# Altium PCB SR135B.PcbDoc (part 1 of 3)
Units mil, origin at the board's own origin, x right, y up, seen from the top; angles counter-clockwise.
Board outline 4100 x 3600 mil, 4 copper layers (Top Layer, Signal Layer 1, Signal Layer 2, Bottom Layer), stack 73.068 mil thick; 169 components, 61 nets, 392 pads, 261 vias.
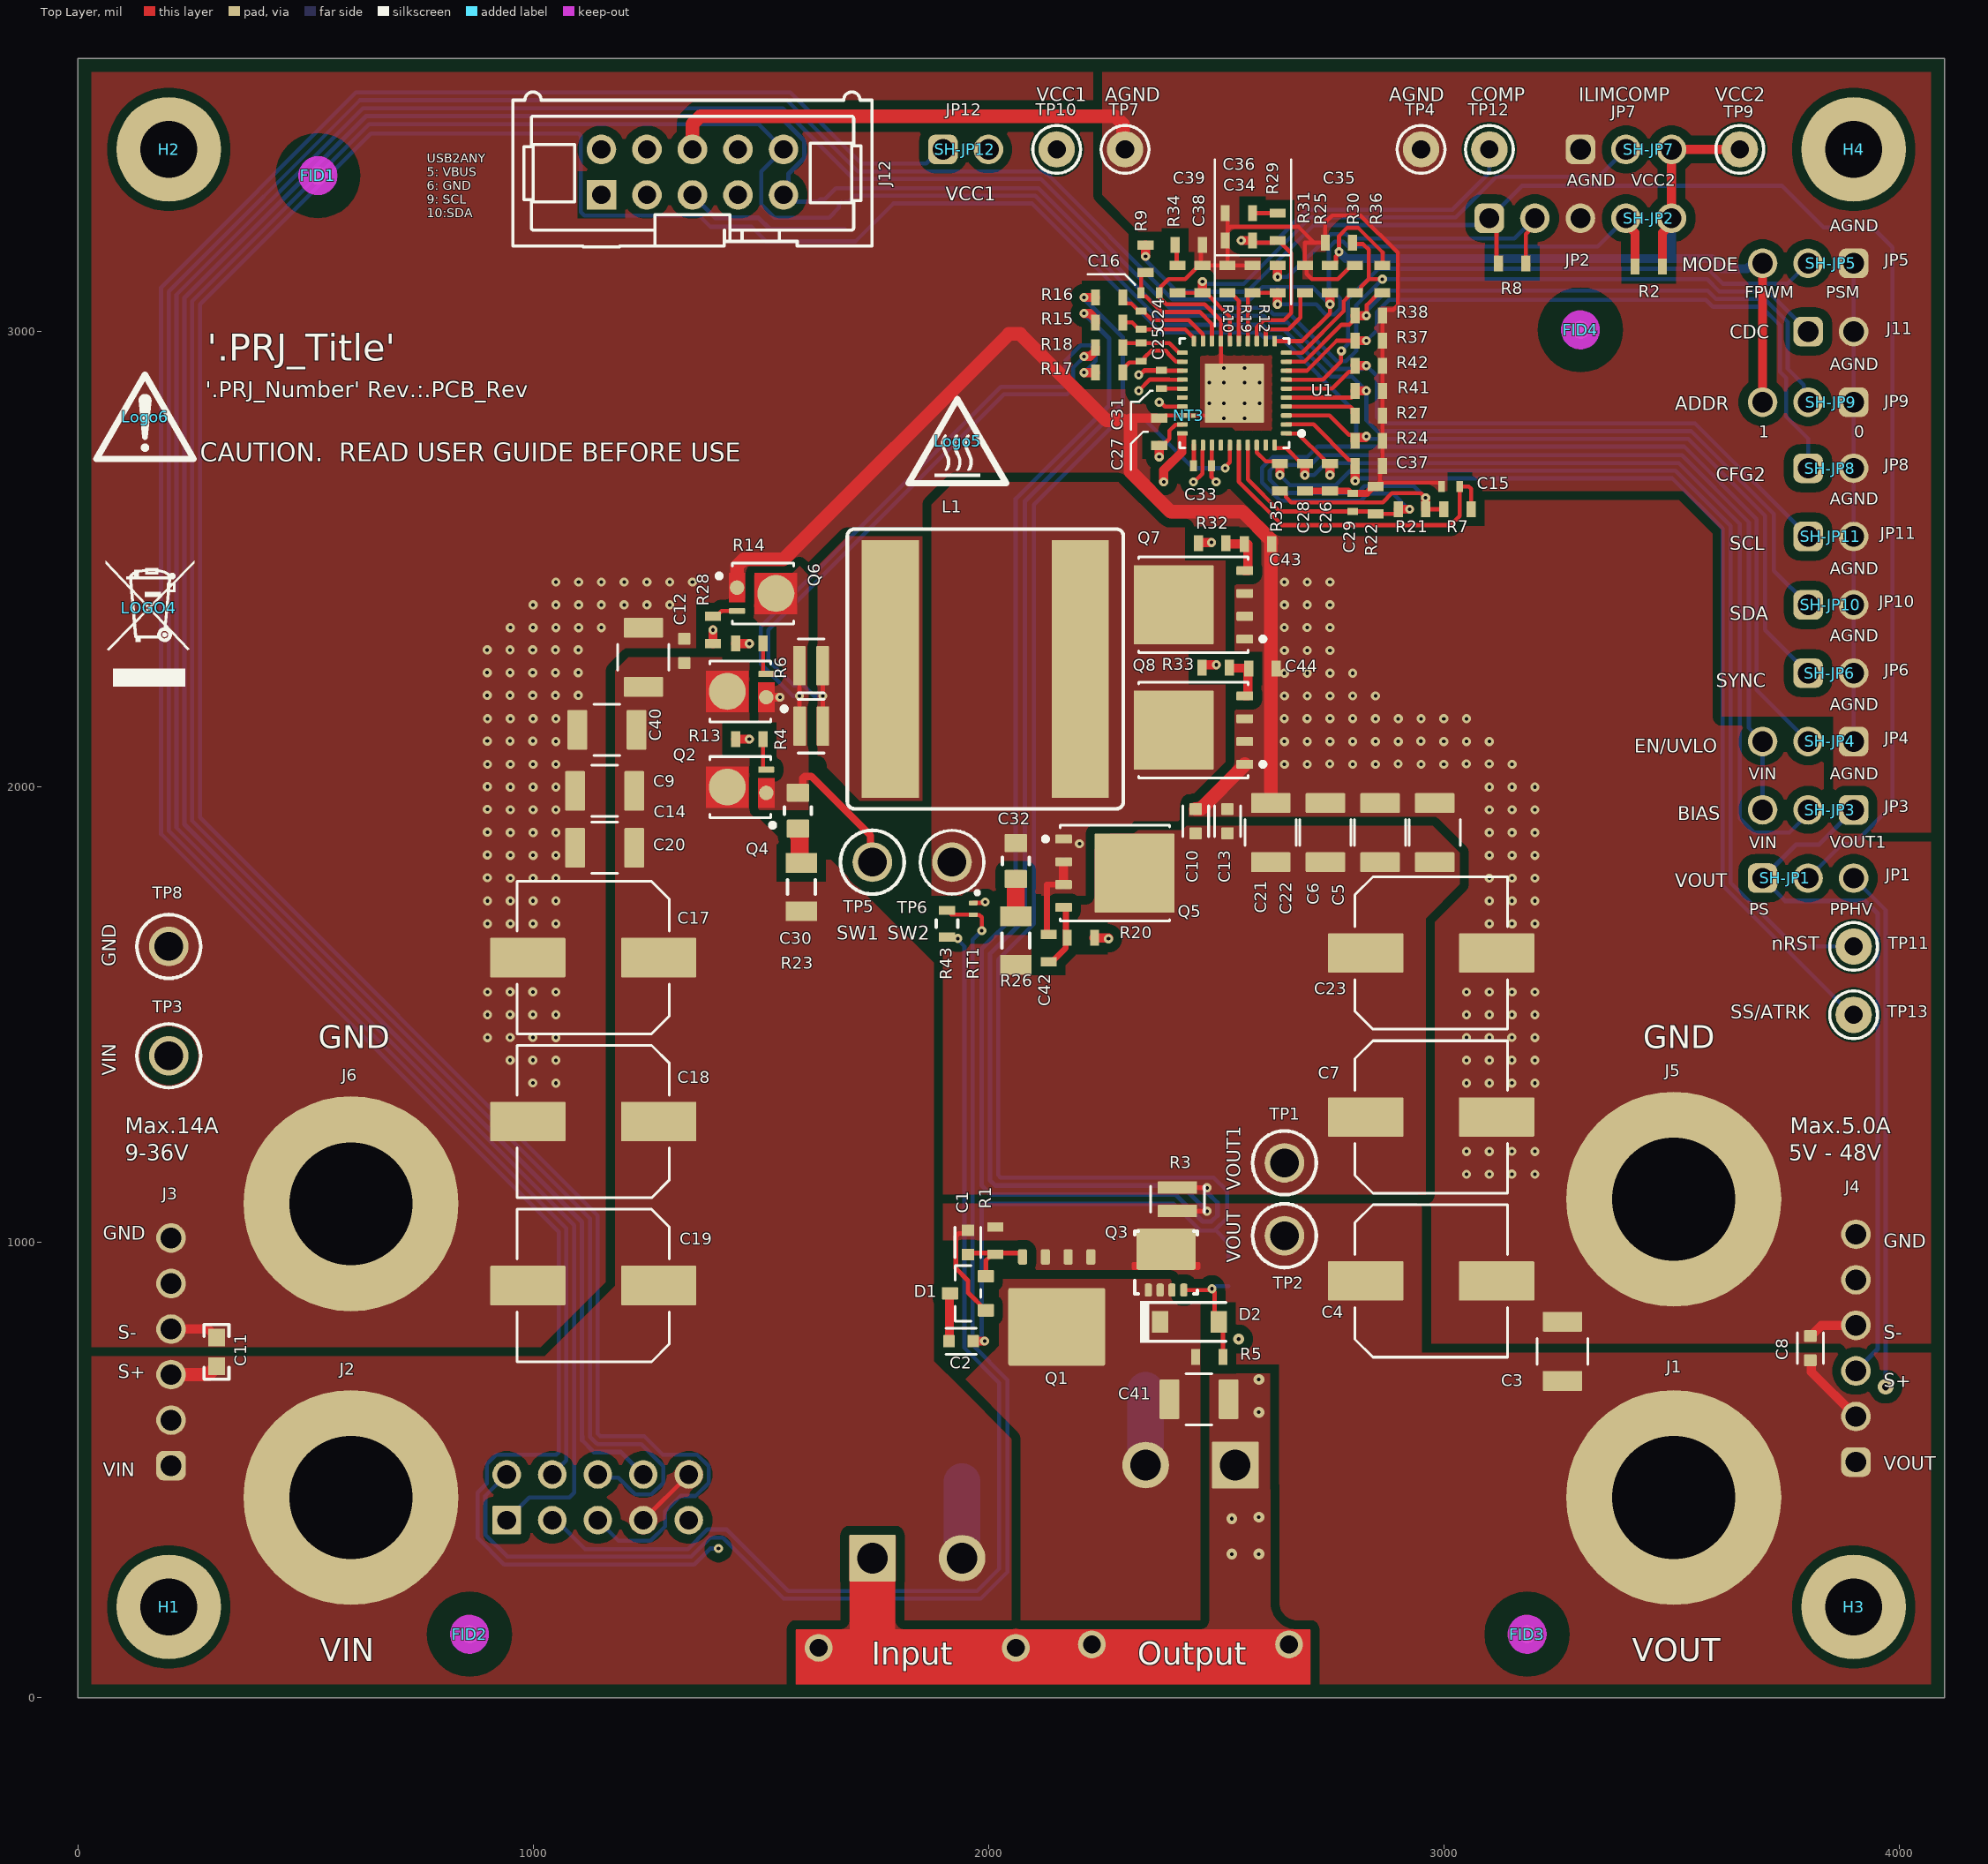
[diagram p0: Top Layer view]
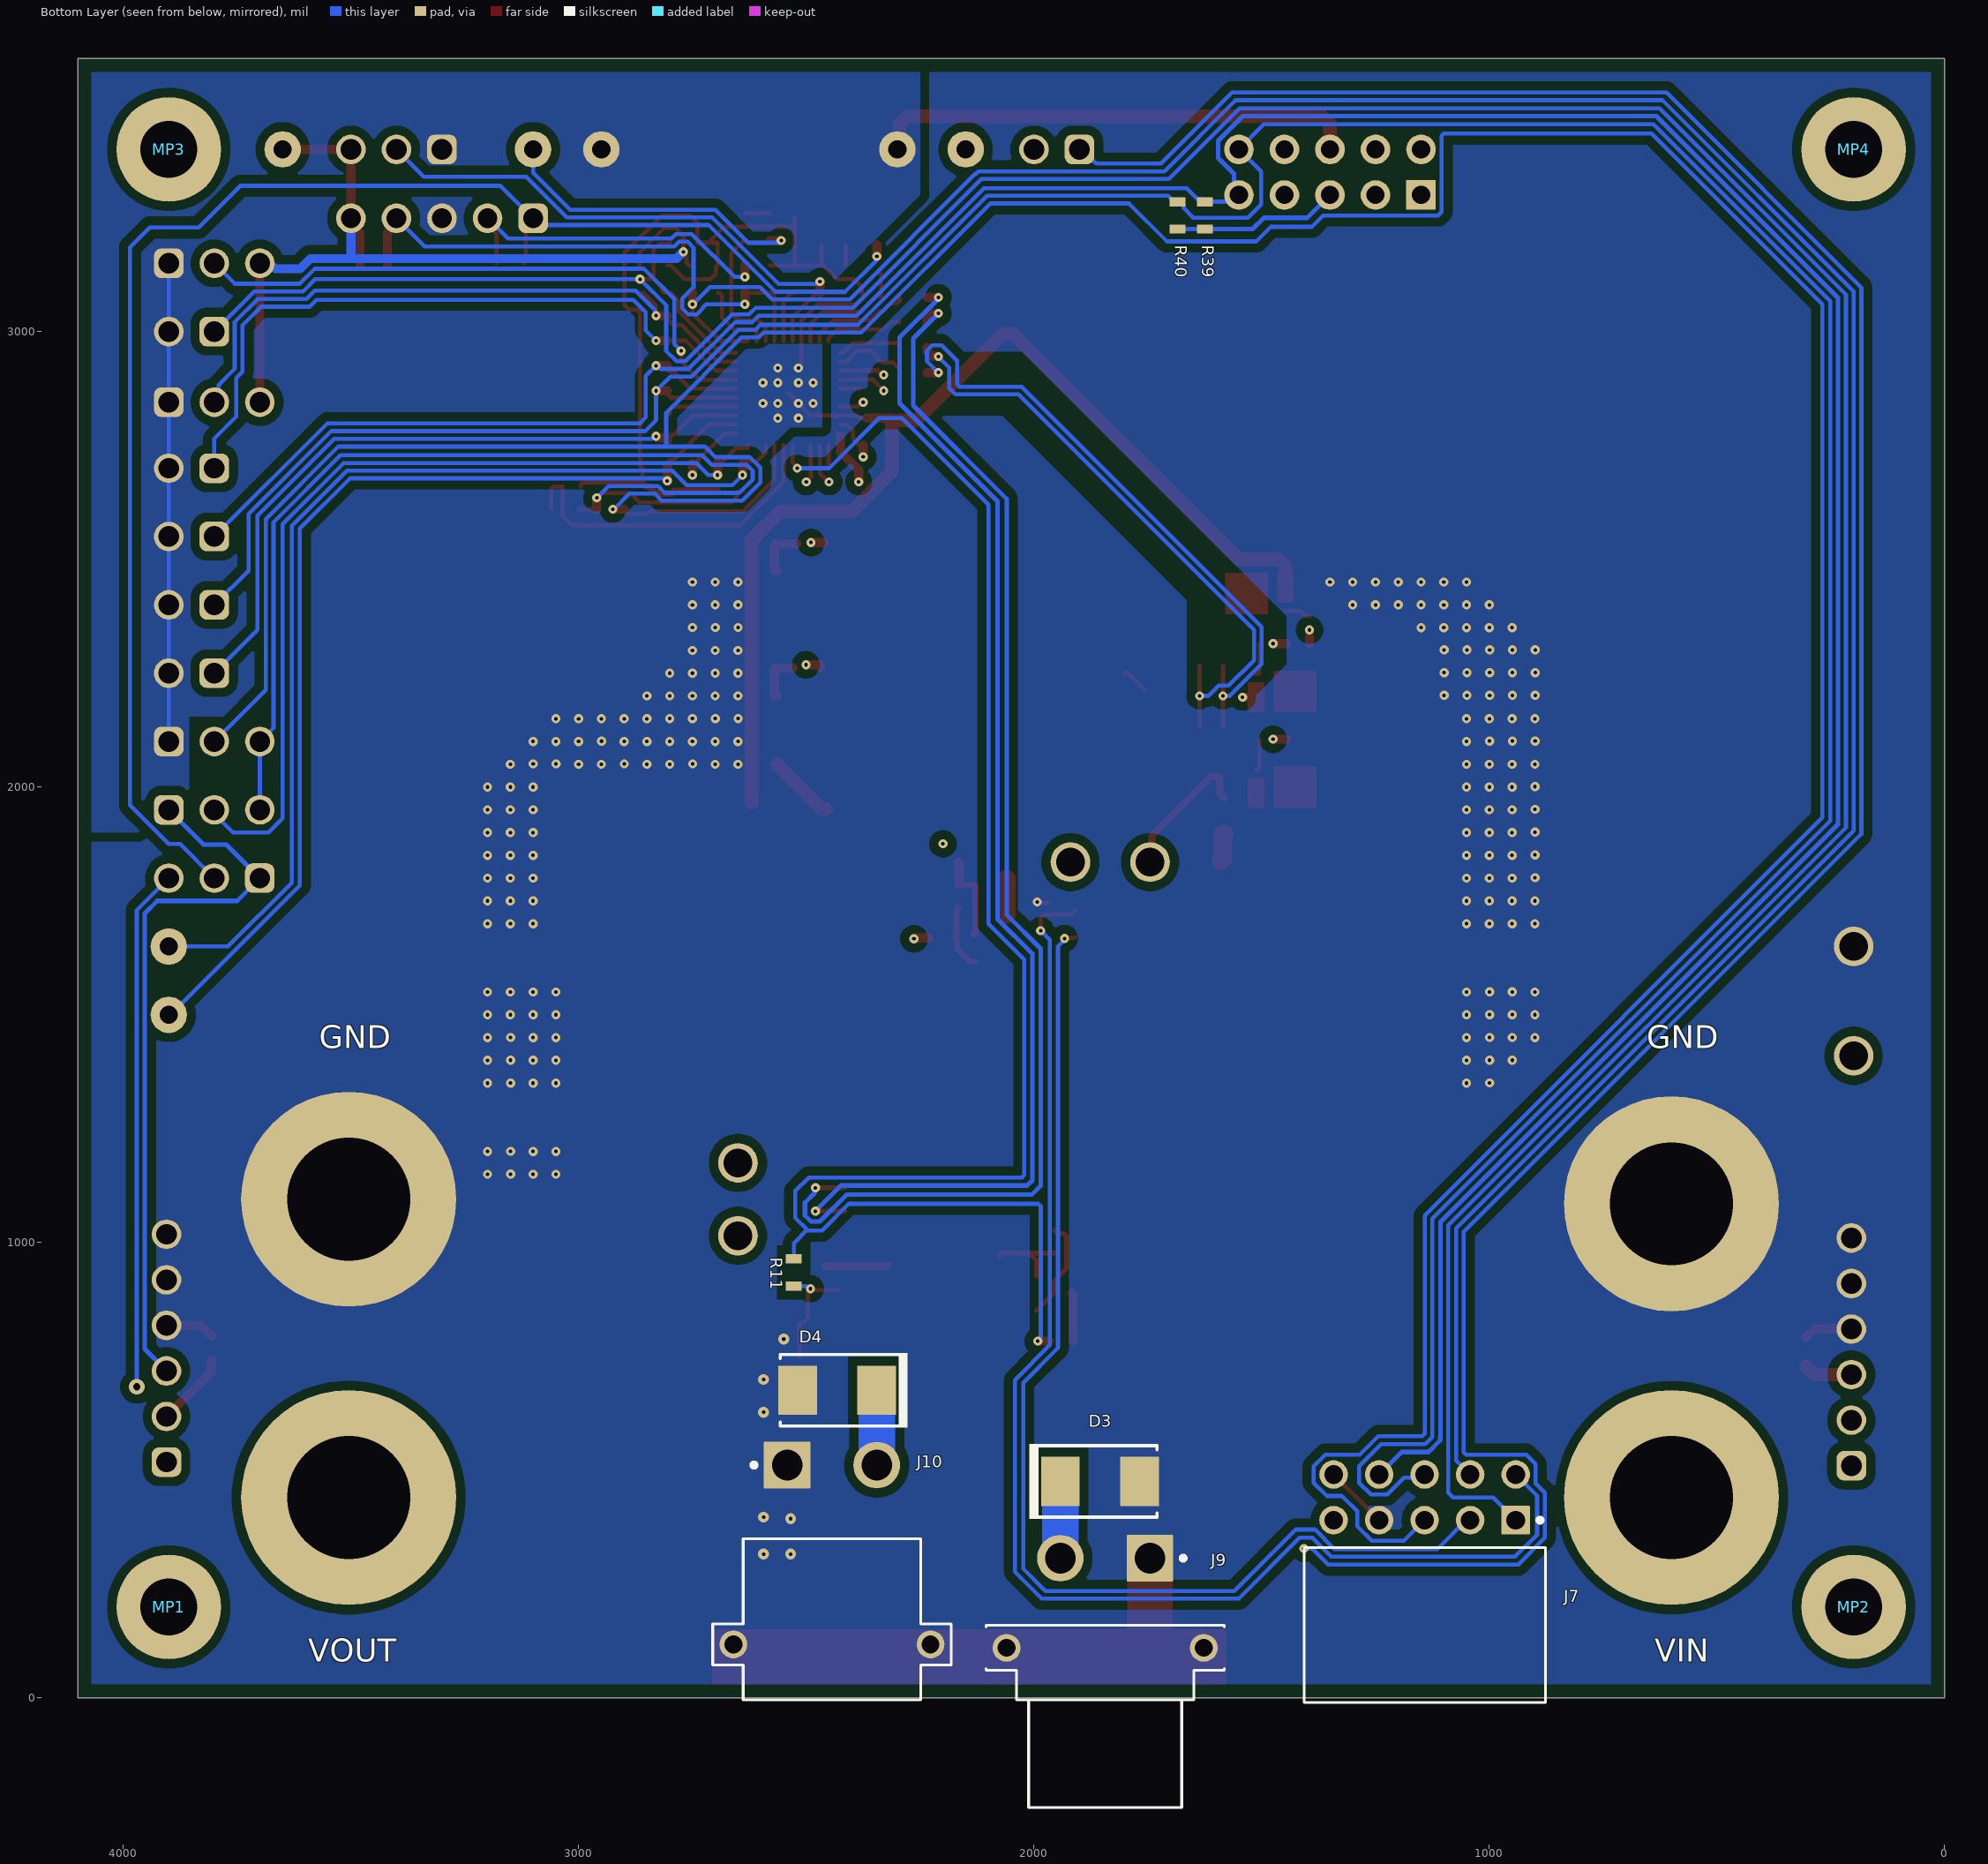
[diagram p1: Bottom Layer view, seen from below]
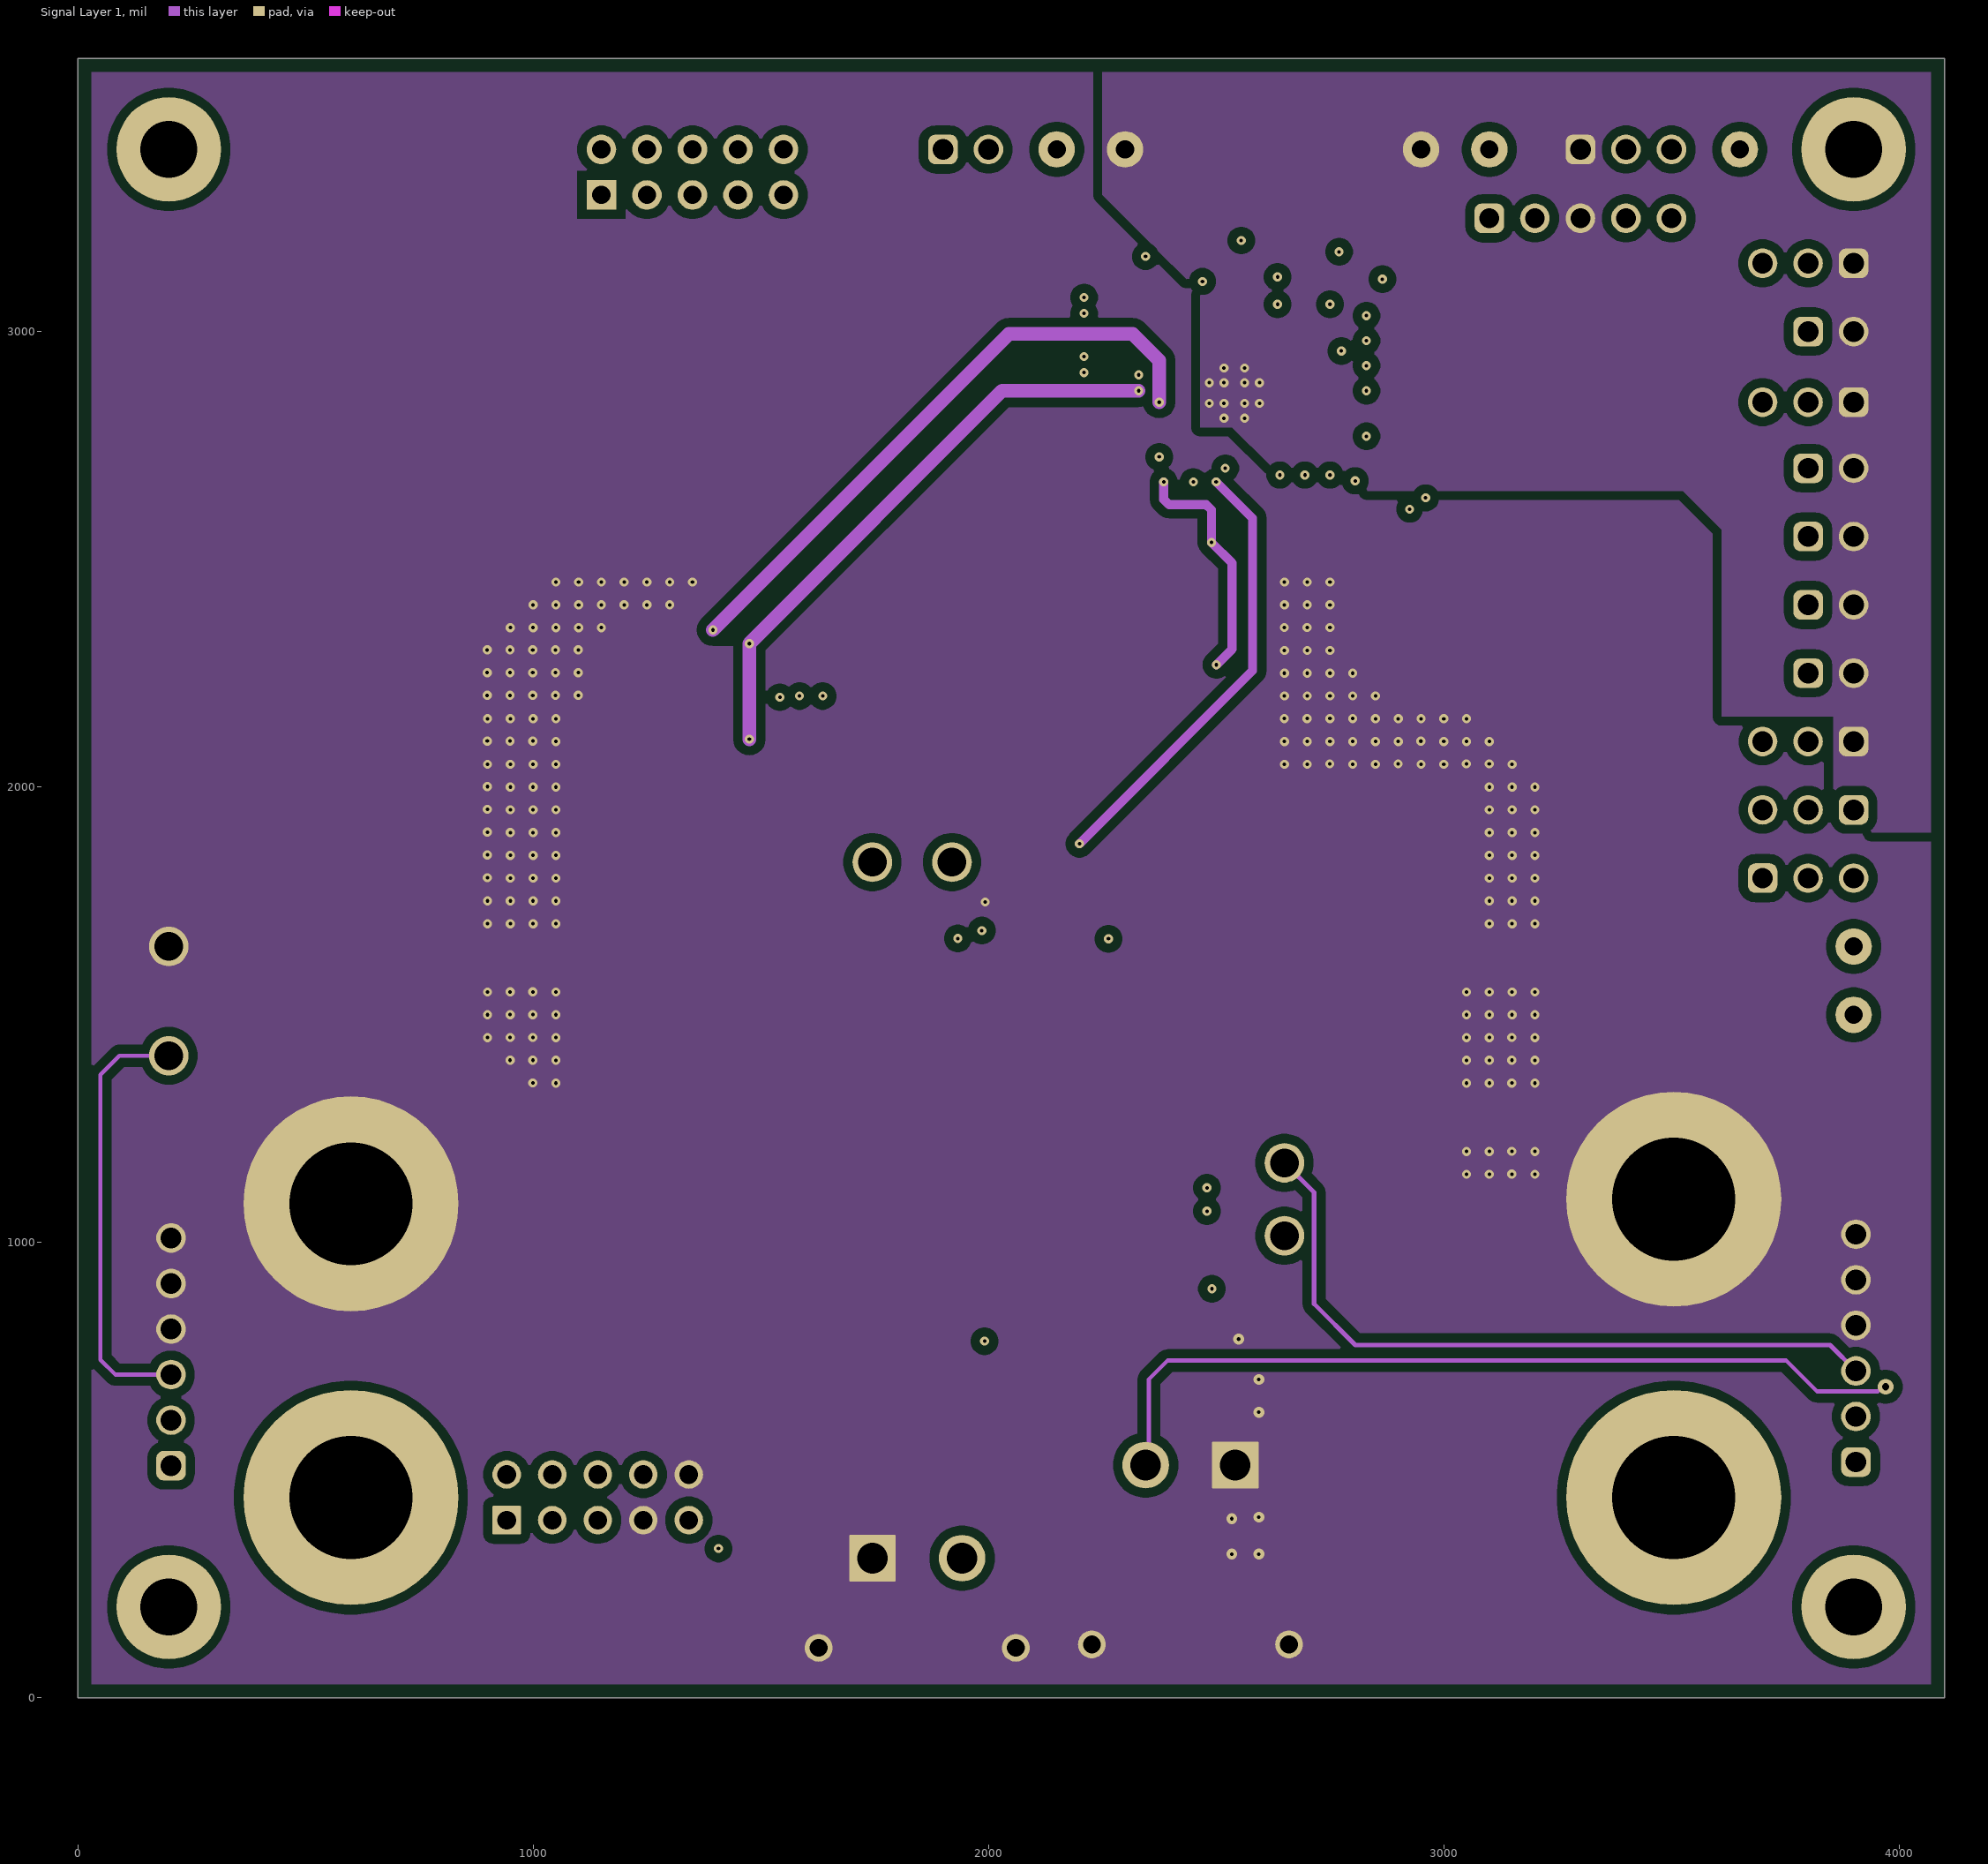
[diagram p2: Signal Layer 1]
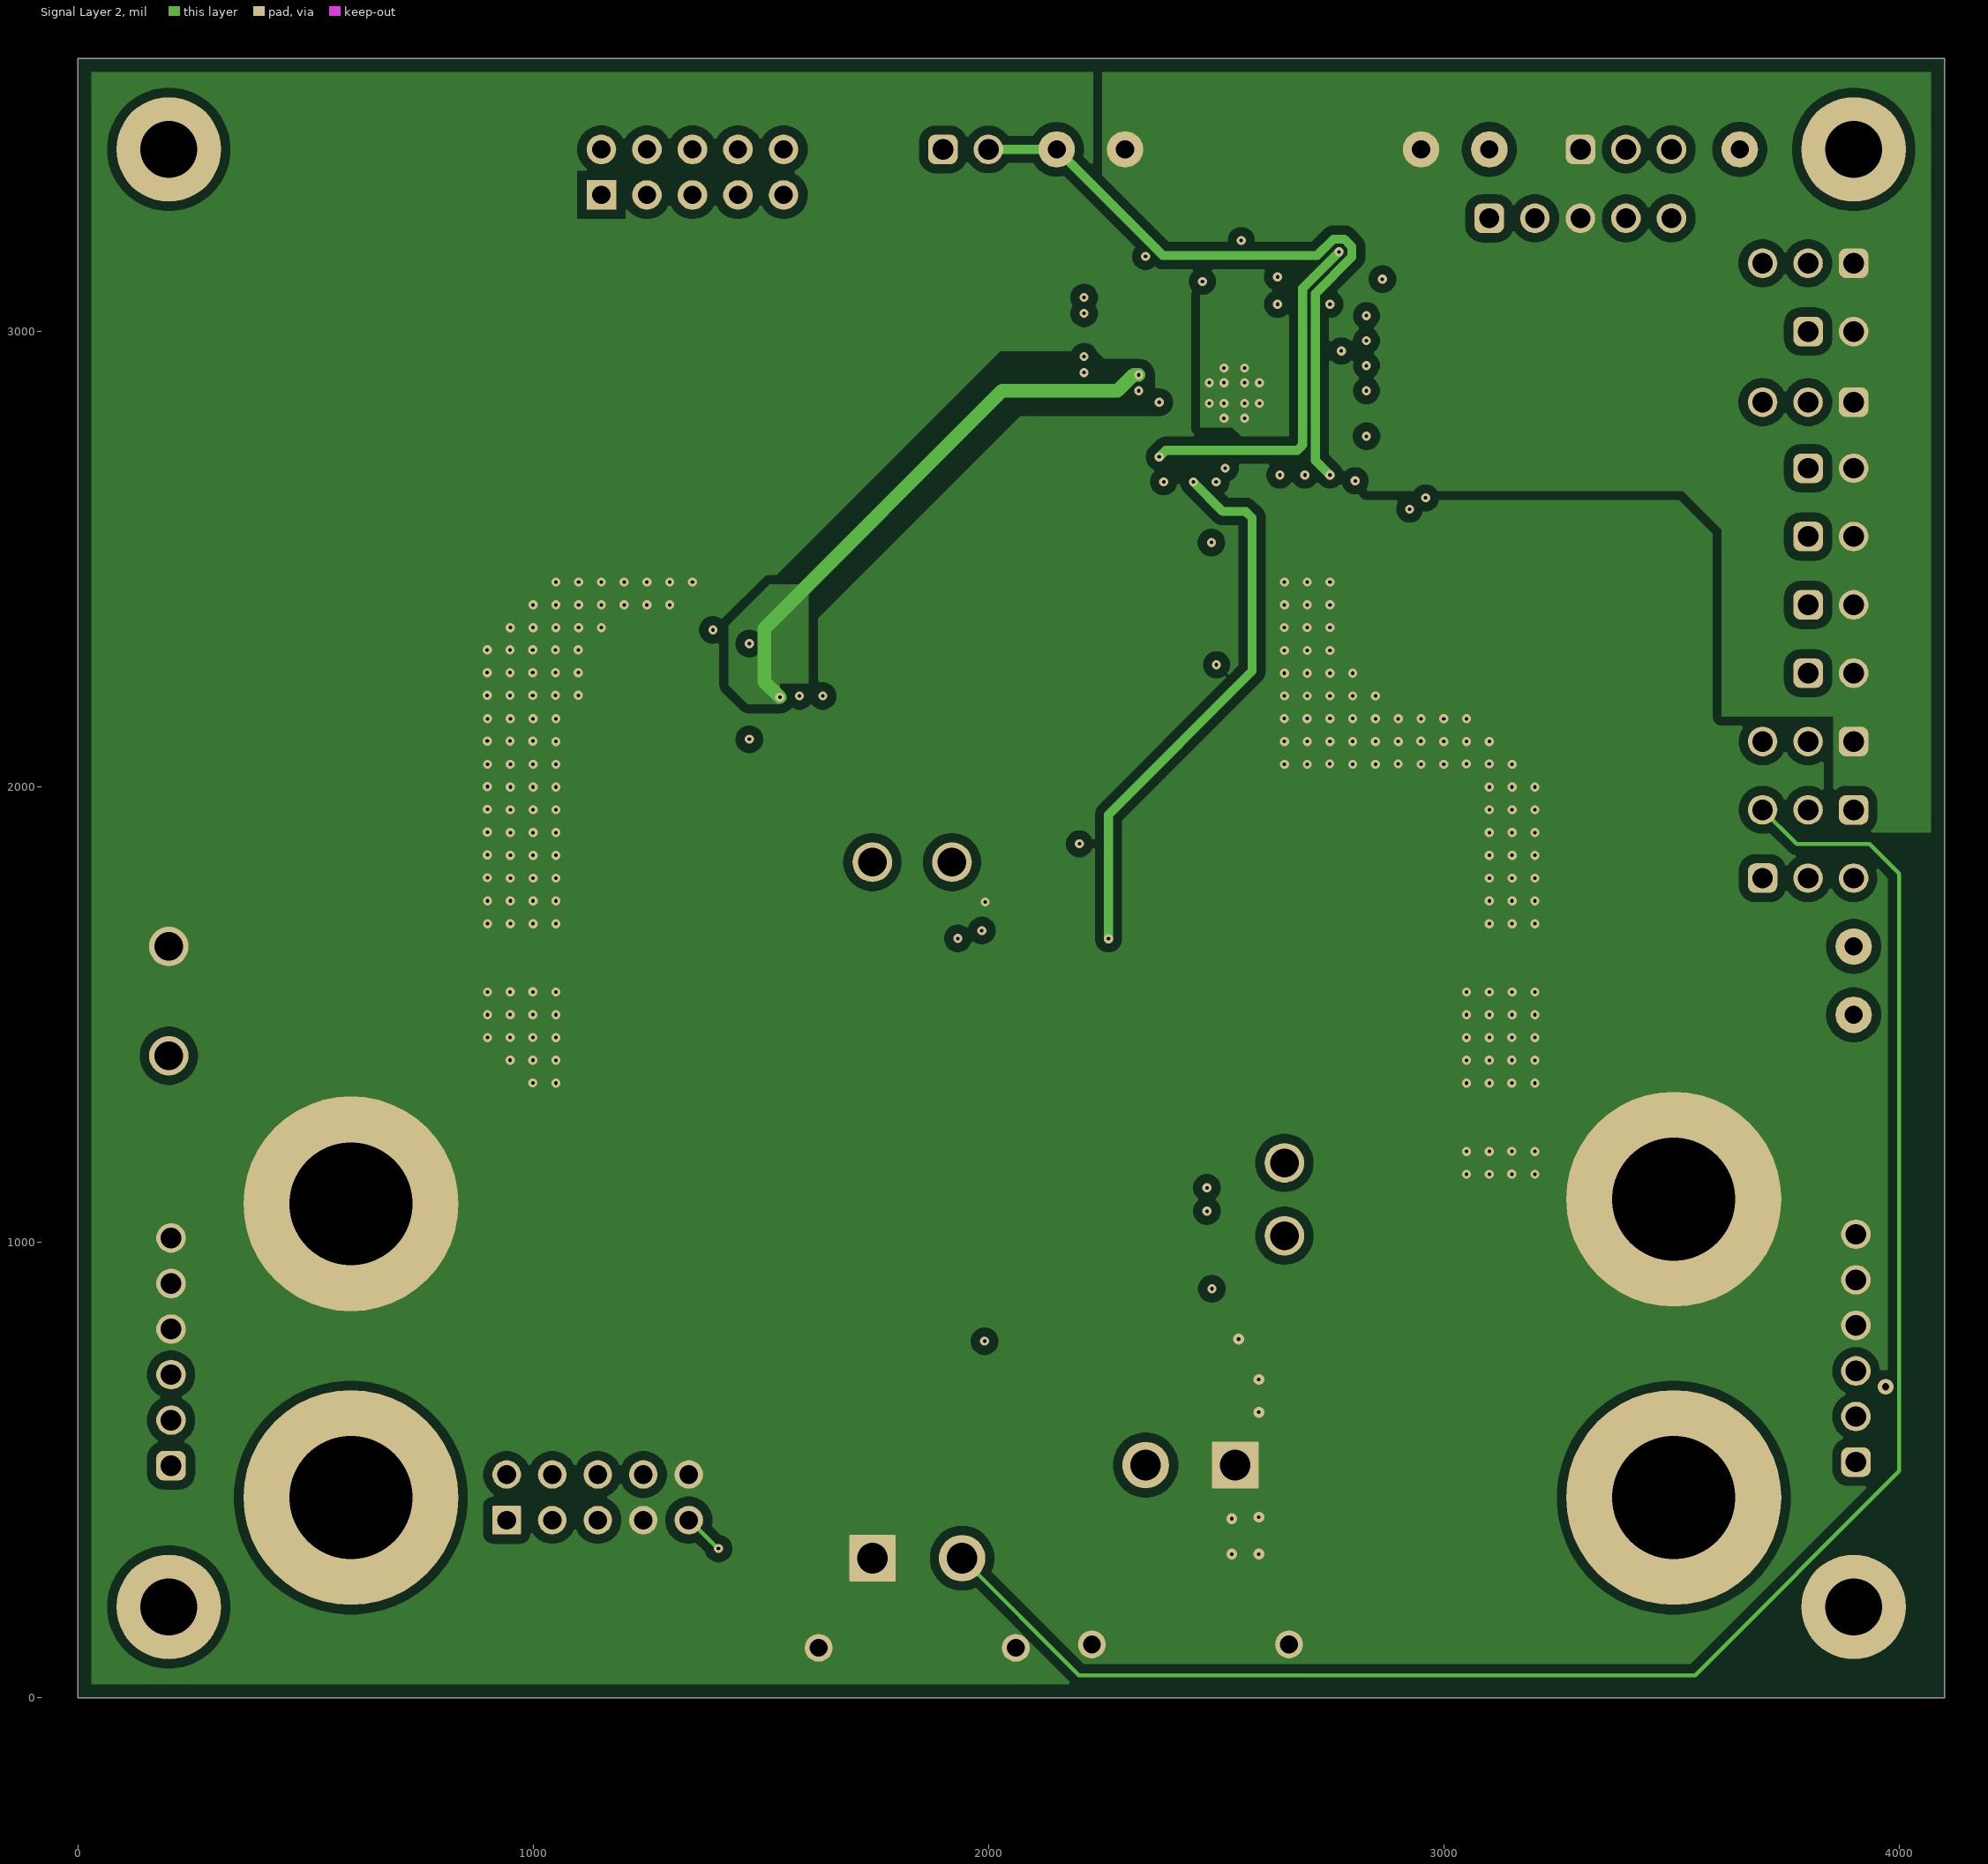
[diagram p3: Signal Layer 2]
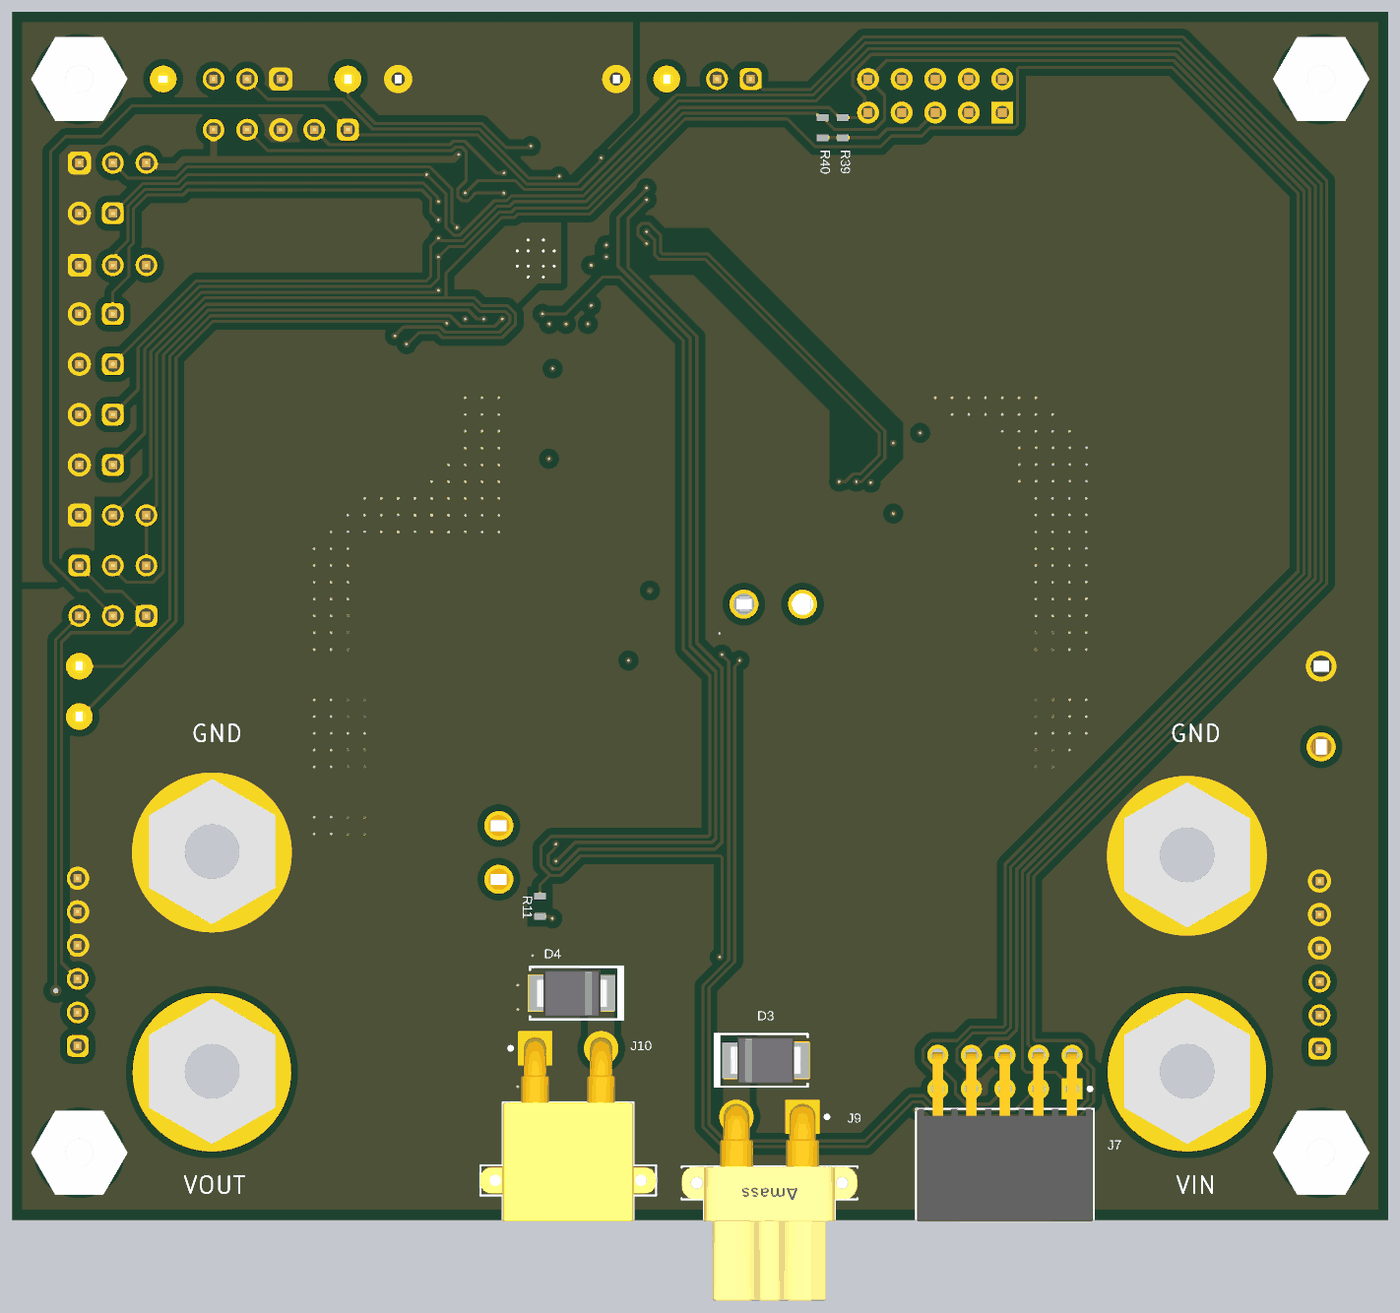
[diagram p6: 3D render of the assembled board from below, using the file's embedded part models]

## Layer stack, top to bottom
Top Solder: solder mask 0.4, Solder Resist, Dk 3.5
Top Layer: signal copper 2.756
Dielectric 1: prepreg 2.8, PP-006, Dk 4.1
Signal Layer 1: signal copper 1.378
Dielectric1: core 59.2, FR-4 High Tg, Dk 4.8
Signal Layer 2: signal copper 1.378
Dielectric 2: prepreg 2.8, PP-006, Dk 4.1
Bottom Layer: signal copper 2.756
Bottom Solder: solder mask 0.4, Solder Resist, Dk 3.5

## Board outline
0,0 0,3600 4100,3600 4100,0

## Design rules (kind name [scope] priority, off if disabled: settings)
AcuteAngle [All] p1: minimum=4.50000000000000E+0001 checktracksonly=FALSE
AssemblyTestPointUsage [All] p1: valid=2
BoardOutlineClearance BoardOutlineClearance_MountingHoles [OnCopper and InComponentClass('Mounting Holes')] p1: gap=30 ignorepadtopadclearanceinfootprint=FALSE
BoardOutlineClearance BoardOutlineClearance_Poly [OnCopper and InPoly] p2: gap=25 ignorepadtopadclearanceinfootprint=FALSE
BoardOutlineClearance [OnCopper and Not InComponentClass('Logo') and not InComponentClass('FiducialMark') and not InRegion(1000,500,4000,800)] p3: gap=30 ignorepadtopadclearanceinfootprint=FALSE
Clearance Clearance_FiducialMark [IsKeepOut and InComponentClass('FiducialMark') vs IsPad and InComponentClass('FiducialMark')] p1: gap=0 ignorepadtopadclearanceinfootprint=FALSE
Clearance Clearance_2 [InNetClass('HV') vs Not InNetClass('HV')] p2: gap=60 ignorepadtopadclearanceinfootprint=FALSE
Clearance Clearance_1 [InNetClass('MV') vs Not InNetClass('MV')] p3: gap=30 ignorepadtopadclearanceinfootprint=FALSE
Clearance Clearance_Keepouts [((IsTrack Or IsArc) And Not InPoly) And IsFree and IsKeepOut vs ((IsTrack Or IsArc) And Not InPoly) And IsFree and IsKeepOut] p4: gap=0 ignorepadtopadclearanceinfootprint=FALSE
Clearance Clearance_BoardEdge_MountingHoles [OnCopper and InComponentClass('Mounting Holes') vs IsKeepOut] p5: gap=40 ignorepadtopadclearanceinfootprint=FALSE except(0: Arc-Hole Track-Hole SMDPad-Hole THPad-Hole Via-Hole Fill-Hole Poly-Hole Region-Hole Text-Hole)
Clearance Clearance_BoardEdge_Poly [OnCopper and InPoly vs IsKeepOut] p6: gap=50 ignorepadtopadclearanceinfootprint=FALSE except(0: Arc-Hole Track-Hole SMDPad-Hole THPad-Hole Via-Hole Fill-Hole Poly-Hole Region-Hole Text-Hole)
Clearance Clearance_BoardEdge [OnCopper and Not InComponentClass('Logo') and not InComponentClass('FiducialMark') and not InRegion(1000,500,4000,800) and Not IsKeepout vs IsKeepOut] p7: gap=50 ignorepadtopadclearanceinfootprint=FALSE
Clearance Clearance_Poly [InPolygon] p8: gap=20 ignorepadtopadclearanceinfootprint=FALSE except(0: Arc-Hole Track-Hole SMDPad-Hole THPad-Hole Via-Hole Fill-Hole Poly-Hole Region-Hole Text-Hole)
Clearance [All] p9: gap=7.87 ignorepadtopadclearanceinfootprint=FALSE except(0: Arc-Hole Track-Hole SMDPad-Hole THPad-Hole Via-Hole Fill-Hole Poly-Hole Region-Hole Text-Hole)
ComponentClearance ComponentClearance_MP [All vs InComponent('MP1') or InComponent('MP2') or InComponent('MP3') or InComponent('MP4')] p1: gap=-1 collisioncheckmode=3 verticalgap=10 showdistances=FALSE
ComponentClearance ComponentClearance_1 [InComponent('NT3')] p2: gap=-1 collisioncheckmode=3 verticalgap=0 showdistances=FALSE
ComponentClearance ComponentClearance_MountingHoles_FiducialMarks [InComponentClass('Mounting Holes') vs InComponentClass('FiducialMark')] p3: gap=50 collisioncheckmode=3 verticalgap=10 showdistances=FALSE
ComponentClearance ComponentClearance_Shunt [InComponentClass('Header') vs InComponentClass('Shunt') or InComponent('SH-JP1') or InComponent('SH-JP2') or InComponent('SH-JP3') or InComponent('SH-JP4') or InComponent('SH-JP5') or InComponent('SH-JP6') or InComponent('SH-JP7') or InComponent('SH-JP8') or InComponent('SH-JP9') or InComponent('SH-JP10') or InComponent('SH-JP11') or InComponent('SH-JP12')] p4: gap=-1 collisioncheckmode=3 verticalgap=0 showdistances=FALSE
ComponentClearance ComponentClearance_Logo [InComponentClass('Logo')] p5: gap=5 collisioncheckmode=3 verticalgap=10 showdistances=FALSE
ComponentClearance ComponentClearance_ScrewToNut [(HasFootprint('NY PMS 440 0025 PH')) vs (HasFootprint('Keystone_1902C'))] p6: gap=-1 collisioncheckmode=3 verticalgap=100000 showdistances=FALSE
ComponentClearance ComponentClearance_MountingHoles [InComponentClass('Mounting Holes')] p7: gap=100 collisioncheckmode=3 verticalgap=10 showdistances=FALSE
ComponentClearance ComponentClearance_SmallPassives [HasFootprint('0201*') or HasFootprint('0402*') or HasFootprint('0508') or HasFootprint('0603*') or HasFootprint('0612') or HasFootprint('0805*') or HasFootprint('0815*') or HasFootprint('0830*') or HasFootprint('1206*') or HasFootprint('1210*') or HasFootprint('1808*') or HasFootprint('1812*') or HasFootprint('1825*') or HasFootprint('2010*') or HasFootprint('2220*') or HasFootprint('2225*') or HasFootprint('2512*') or HasFootprint('2728*') or HasFootprint('3518*') vs HasFootprint('0201*') or HasFootprint('0402*') or HasFootprint('0508') or HasFootprint('0603*') or HasFootprint('0612') or HasFootprint('0805*') or HasFootprint('0815*') or HasFootprint('0830*') or HasFootprint('1206*') or HasFootprint('1210*') or HasFootprint('1808*') or HasFootprint('1812*') or HasFootprint('1825*') or HasFootprint('2010*') or HasFootprint('2220*') or HasFootprint('2225*') or HasFootprint('2512*') or HasFootprint('2728*') or HasFootprint('3518*')] p8: gap=17.5 collisioncheckmode=3 verticalgap=17.5 showdistances=FALSE
ComponentClearance ComponentClearance_THtoSMT [IsThruComponent vs IsSMTComponent] p9: gap=10 collisioncheckmode=3 verticalgap=10 showdistances=FALSE
ComponentClearance ComponentClearance_THtoTH [IsThruComponent vs IsThruComponent] p10: gap=20 collisioncheckmode=3 verticalgap=20 showdistances=FALSE
ComponentClearance [All] p11: gap=10 collisioncheckmode=3 verticalgap=10 showdistances=FALSE
DiffPairsRouting [All] p1: maxlimit=100 minlimit=10 mostfreqgap=10 toplayer_minwidth=15 toplayer_maxwidth=15 toplayer_prefwidth=15 midlayer1_minwidth=15 midlayer1_maxwidth=15 midlayer1_prefwidth=15 midlayer2_minwidth=15 midlayer2_maxwidth=15 midlayer2_prefwidth=15 bottomlayer_minwidth=15 bottomlayer_maxwidth=15 bottomlayer_prefwidth=15 maxuncoupledlength=1000
FabricationTestPointUsage TestPointUsage [All] p1: valid=2 allowmultiple=FALSE
FabricationTestpoint Testpoint [All] p1: side=3 testpointundercomponent=TRUE minsize=40 maxsize=100 preferedsize=60 minholesize=0 maxholesize=40 preferedholesize=32 testpointgrid=1 allowsidetop=TRUE allowsidebottom=TRUE usegrid=TRUE gridtolerance=0.01
FanoutControl Fanout_LCC [IsLCC] p1: bgadir=Out bgaviamode=Centered fanoutstyle=Auto fanoutdirection=Alternating viagrid=1 // Fanout_LCC (Default Rule)
FanoutControl Fanout_BGA [IsBGA] p2: bgadir=Out bgaviamode=Centered fanoutstyle=Auto fanoutdirection=Alternating viagrid=1 // Fanout_BGA (Default Rule)
FanoutControl Fanout_Default [All] p4: bgadir=Out bgaviamode=Centered fanoutstyle=Auto fanoutdirection=Alternating viagrid=1 // Fanout_Default (Default Rule)
FanoutControl Fanout_Small [(CompPinCount < 5)] p5: bgadir=Out bgaviamode=Centered fanoutstyle=Auto fanoutdirection=OutThenIn viagrid=1 // Fanout_Small (Default Rule)
Height [All] p1: minheight=0 maxheight=3000 prefheight=500
HoleSize [All] p1: absolutevalues=TRUE maxlimit=271 minlimit=7.87 maxpercent=80.000 minpercent=20.000
MinimumAnnularRing MinimumAnnularRing_ThermalPadVias [IsVia and InAnyComponent] p1: minimumring=5.91
MinimumAnnularRing [All] p2: minimumring=6
MinimumSolderMaskSliver MinimumSolderMaskSliver_Logo [InComponentClass('Logo') vs InComponentClass('Logo')] p1: minsoldermaskwidth=0.7
MinimumSolderMaskSliver [All] p2: minsoldermaskwidth=3.94
PlaneConnect [All] p1: planeconnectstyle=Direct reliefexpansion=10 reliefentries=4 reliefconductorwidth=10 reliefairgap=10
PolygonConnect PolygonConnect_15 [All vs IsNamedPolygon('C109_2') Or  IsNamedPolygon('C107_2') Or  IsNamedPolygon('HV') Or  IsNamedPolygon('Q203_5') Or  IsNamedPolygon('C107_2') Or  IsNamedPolygon('HS') Or  IsNamedPolygon('Q201_5') Or  IsNamedPolygon('Q203_5') Or  IsNamedPolygon('C106_2') Or  IsNamedPolygon('C108_2') Or  IsNamedPolygon('Vout') Or  IsNamedPolygon('Q203_5') Or  IsNamedPolygon('C108_2') Or  IsNamedPolygon('C113_2') Or  IsNamedPolygon('Q203_5') Or  IsNamedPolygon('Q201_5') Or  IsNamedPolygon('C107_2') Or  IsNamedPolygon('C102_1') Or  IsNamedPolygon('SGND') Or  IsNamedPolygon('GND') Or  IsNamedPolygon('SGND') Or  IsNamedPolygon('GND') Or  IsNamedPolygon('IN+') Or  IsNamedPolygon('IN+') Or  IsNamedPolygon('Q201_5') Or  IsNamedPolygon('Q201_5') Or  IsNamedPolygon('SGND') Or  IsNamedPolygon('SGND') Or  IsNamedPolygon('Vout') Or  IsNamedPolygon('Vout') Or  IsNamedPolygon('IN+') Or  IsNamedPolygon('GND') Or  IsNamedPolygon('IN+') Or  IsNamedPolygon('GND')] p1: connectstyle=Direct reliefconductorwidth=10 reliefentries=4 polygonreliefangle="90 Angle" airgapwidth=10
PolygonConnect PolygonConnect_14 [All vs IsNamedPolygon('C106_2') Or  IsNamedPolygon('C107_2') Or  IsNamedPolygon('C107_2') Or  IsNamedPolygon('C107_2') Or  IsNamedPolygon('C102_1') Or  IsNamedPolygon('Q203_5') Or  IsNamedPolygon('Vout') Or  IsNamedPolygon('Q203_5') Or  IsNamedPolygon('Q203_5') Or  IsNamedPolygon('Q201_5') Or  IsNamedPolygon('C108_2') Or  IsNamedPolygon('Q203_5') Or  IsNamedPolygon('HS') Or  IsNamedPolygon('HV') Or  IsNamedPolygon('C108_2') Or  IsNamedPolygon('Q201_5') Or  IsNamedPolygon('C109_2') Or  IsNamedPolygon('Q201_5') Or  IsNamedPolygon('Q201_5') Or  IsNamedPolygon('C113_2')] p2: connectstyle=Direct reliefconductorwidth=10 reliefentries=4 polygonreliefangle="90 Angle" airgapwidth=10
PolygonConnect PolygonConnect_13 [All vs IsNamedPolygon('C102_1') Or  IsNamedPolygon('HV') Or  IsNamedPolygon('C107_2') Or  IsNamedPolygon('C109_2') Or  IsNamedPolygon('C107_2') Or  IsNamedPolygon('C108_2') Or  IsNamedPolygon('C106_2') Or  IsNamedPolygon('C108_2') Or  IsNamedPolygon('C113_2') Or  IsNamedPolygon('C107_2')] p3: connectstyle=Direct reliefconductorwidth=10 reliefentries=4 polygonreliefangle="90 Angle" airgapwidth=10
PolygonConnect PolygonConnect_12 [All vs IsNamedPolygon('C107_2') Or  IsNamedPolygon('C113_2') Or  IsNamedPolygon('C106_2') Or  IsNamedPolygon('C107_2') Or  IsNamedPolygon('C107_2') Or  IsNamedPolygon('C102_1')] p4: connectstyle=Direct reliefconductorwidth=10 reliefentries=4 polygonreliefangle="90 Angle" airgapwidth=10
PolygonConnect PolygonConnect_11 [All vs IsNamedPolygon('C106_2') Or  IsNamedPolygon('C102_1') Or  IsNamedPolygon('C107_2') Or  IsNamedPolygon('C107_2') Or  IsNamedPolygon('C107_2')] p5: connectstyle=Direct reliefconductorwidth=10 reliefentries=4 polygonreliefangle="90 Angle" airgapwidth=10
PolygonConnect PolygonConnect_10 [All vs IsNamedPolygon('C106_2')] p6: connectstyle=Direct reliefconductorwidth=10 reliefentries=4 polygonreliefangle="90 Angle" airgapwidth=10
PolygonConnect PolygonConnect_9 [All vs IsNamedPolygon('C11_1') Or  IsNamedPolygon('Vin') Or  IsNamedPolygon('Vin') Or  IsNamedPolygon('5V') Or  IsNamedPolygon('D6_2') Or  IsNamedPolygon('Q3_3') Or  IsNamedPolygon('GND2') Or  IsNamedPolygon('GND2') Or  IsNamedPolygon('GND') Or  IsNamedPolygon('Q3_4') Or  IsNamedPolygon('12V5') Or  IsNamedPolygon('GND') Or  IsNamedPolygon('12V5') Or  IsNamedPolygon('D3_1')] p7: connectstyle=Direct reliefconductorwidth=10 reliefentries=4 polygonreliefangle="90 Angle" airgapwidth=10
PolygonConnect PolygonConnect_8 [All vs IsNamedPolygon('C11_1') Or  IsNamedPolygon('Vin') Or  IsNamedPolygon('12V5') Or  IsNamedPolygon('Q3_3') Or  IsNamedPolygon('GND2') Or  IsNamedPolygon('GND2') Or  IsNamedPolygon('5V') Or  IsNamedPolygon('Q3_4') Or  IsNamedPolygon('12V5')] p8: connectstyle=Direct reliefconductorwidth=10 reliefentries=4 polygonreliefangle="90 Angle" airgapwidth=10
PolygonConnect PolygonConnect_7 [All vs IsNamedPolygon('GND2') Or  IsNamedPolygon('GND2') Or  IsNamedPolygon('5V') Or  IsNamedPolygon('12V5') Or  IsNamedPolygon('12V5') Or  IsNamedPolygon('C11_1')] p9: connectstyle=Direct reliefconductorwidth=10 reliefentries=4 polygonreliefangle="90 Angle" airgapwidth=10
PolygonConnect PolygonConnect_6 [All vs IsNamedPolygon('GND2') Or  IsNamedPolygon('SGND') Or  IsNamedPolygon('GND1') Or  IsNamedPolygon('C901_1') Or  IsNamedPolygon('SGND') Or  IsNamedPolygon('GND2') Or  IsNamedPolygon('GND1')] p10: connectstyle=Direct reliefconductorwidth=10 reliefentries=4 polygonreliefangle="90 Angle" airgapwidth=10
PolygonConnect PolygonConnect_5 [All vs IsNamedPolygon('GND1') Or  IsNamedPolygon('GND1')] p11: connectstyle=Direct reliefconductorwidth=10 reliefentries=4 polygonreliefangle="90 Angle" airgapwidth=10
PolygonConnect PolygonConnect_4 [All vs IsNamedPolygon('C21_1') Or  IsNamedPolygon('C5_1') Or  IsNamedPolygon('C12_2') Or  IsNamedPolygon('C2_2') Or  IsNamedPolygon('C13_1') Or  IsNamedPolygon('C28_1') Or  IsNamedPolygon('C6_1') Or  IsNamedPolygon('GND') Or  IsNamedPolygon('GND2') Or  IsNamedPolygon('C14_1') Or  IsNamedPolygon('C13_1') Or  IsNamedPolygon('Q1_3') Or  IsNamedPolygon('C14_1') Or  IsNamedPolygon('C5_1') Or  IsNamedPolygon('GND2') Or  IsNamedPolygon('C28_1') Or  IsNamedPolygon('D5_2') Or  IsNamedPolygon('D6_2') Or  IsNamedPolygon('D2_1') Or  IsNamedPolygon('C12_2') Or  IsNamedPolygon('D2_1') Or  IsNamedPolygon('C4_1') Or  IsNamedPolygon('C4_1') Or  IsNamedPolygon('C2_2') Or  IsNamedPolygon('GND') Or  IsNamedPolygon('C33_1') Or  IsNamedPolygon('C9_1')] p12: connectstyle=Direct reliefconductorwidth=10 reliefentries=4 polygonreliefangle="90 Angle" airgapwidth=10
PolygonConnect PolygonConnect_3 [All vs IsNamedPolygon('C28_1') Or  IsNamedPolygon('C12_2') Or  IsNamedPolygon('C28_1') Or  IsNamedPolygon('C9_1') Or  IsNamedPolygon('D5_2') Or  IsNamedPolygon('C12_2') Or  IsNamedPolygon('C2_2') Or  IsNamedPolygon('C14_1') Or  IsNamedPolygon('C4_1') Or  IsNamedPolygon('C14_1') Or  IsNamedPolygon('D6_2') Or  IsNamedPolygon('GND2') Or  IsNamedPolygon('Q1_3') Or  IsNamedPolygon('C5_1') Or  IsNamedPolygon('D2_1') Or  IsNamedPolygon('C4_1') Or  IsNamedPolygon('C13_1') Or  IsNamedPolygon('C5_1') Or  IsNamedPolygon('C13_1') Or  IsNamedPolygon('C33_1') Or  IsNamedPolygon('D2_1') Or  IsNamedPolygon('GND') Or  IsNamedPolygon('GND') Or  IsNamedPolygon('GND2') Or  IsNamedPolygon('C2_2') Or  IsNamedPolygon('C6_1') Or  IsNamedPolygon('C21_1')] p13: connectstyle=Direct reliefconductorwidth=10 reliefentries=4 polygonreliefangle="90 Angle" airgapwidth=10
PolygonConnect PolygonConnect_2 [All vs IsNamedPolygon('C21_1') Or  IsNamedPolygon('C4_1') Or  IsNamedPolygon('D5_2') Or  IsNamedPolygon('C5_1') Or  IsNamedPolygon('C14_1') Or  IsNamedPolygon('C13_1') Or  IsNamedPolygon('C4_1') Or  IsNamedPolygon('C33_1') Or  IsNamedPolygon('C12_2') Or  IsNamedPolygon('D2_1') Or  IsNamedPolygon('C2_2') Or  IsNamedPolygon('C28_1') Or  IsNamedPolygon('C12_2') Or  IsNamedPolygon('D2_1') Or  IsNamedPolygon('C5_1') Or  IsNamedPolygon('Q1_3') Or  IsNamedPolygon('GND') Or  IsNamedPolygon('D6_2') Or  IsNamedPolygon('C6_1') Or  IsNamedPolygon('C2_2') Or  IsNamedPolygon('C14_1') Or  IsNamedPolygon('C28_1') Or  IsNamedPolygon('C13_1') Or  IsNamedPolygon('C9_1') Or  IsNamedPolygon('GND')] p14: connectstyle=Direct reliefconductorwidth=10 reliefentries=4 polygonreliefangle="90 Angle" airgapwidth=10
PolygonConnect PolygonConnect_1 [All vs IsNamedPolygon('C28_1') Or  IsNamedPolygon('D5_2') Or  IsNamedPolygon('C5_1') Or  IsNamedPolygon('C5_1') Or  IsNamedPolygon('D2_1') Or  IsNamedPolygon('C21_1') Or  IsNamedPolygon('C9_1') Or  IsNamedPolygon('C4_1') Or  IsNamedPolygon('C14_1') Or  IsNamedPolygon('C28_1') Or  IsNamedPolygon('C6_1') Or  IsNamedPolygon('C12_2') Or  IsNamedPolygon('C33_1') Or  IsNamedPolygon('C4_1') Or  IsNamedPolygon('C13_1') Or  IsNamedPolygon('C12_2') Or  IsNamedPolygon('D6_2') Or  IsNamedPolygon('C2_2') Or  IsNamedPolygon('C14_1') Or  IsNamedPolygon('D2_1') Or  IsNamedPolygon('C2_2') Or  IsNamedPolygon('C13_1')] p15: connectstyle=Direct reliefconductorwidth=10 reliefentries=4 polygonreliefangle="90 Angle" airgapwidth=10
PolygonConnect [All] p16: connectstyle=Direct reliefconductorwidth=10 reliefentries=4 polygonreliefangle="90 Angle" airgapwidth=10
RoutingVias ThermalPadVias [IsVia and InAnyComponent] p1: holewidth=7.87 width=19.68 viastyle="Through Hole" minholewidth=7.87 minwidth=19.68 maxholewidth=12.99 maxwidth=23.62
RoutingVias [All] p2: holewidth=16 width=34 viastyle="Through Hole" minholewidth=7.87 minwidth=20 maxholewidth=40 maxwidth=65
SilkToBoardRegionClearance [Not ((IsComment or IsDesignator) And (Hide <> 'False')) and not InRegion(1000,500,4000,800)] p1:
SilkToSilkClearance SilkToSilkClearance_Pb-FreeLogo [(HasFootprint('Pb-Free_Overlay_Medium') OR HasFootprint('Pb-Free_Overlay_Small')) vs (HasFootprint('Pb-Free_Overlay_Medium') OR HasFootprint('Pb-Free_Overlay_Small'))] p1: silktosilkclearance=0
SilkToSilkClearance [All] p2: silktosilkclearance=4
SilkToSolderMaskClearance SilkToComponentPadClearance [IsPad and InAnycomponent] p1: minsilkscreentomaskgap=5 clearancetoexposedcopper=TRUE
SilkToSolderMaskClearance "Silk to Solder Mask Opening" [All] p2: minsilkscreentomaskgap=4 clearancetoexposedcopper=FALSE
SolderMaskExpansion [All] p1: expansion=1.97 istentingtop=FALSE
SupplyNets "Schematic Supply Nets_2" [InNet('AGND')] p1: voltage=0.000
SupplyNets "Schematic Supply Nets_1" [InNet('GND')] p2: voltage=0.000
SupplyNets "Schematic Supply Nets" [InNet('VBUS')] p3: voltage=0.000
Width [All] p1: maxlimit=100 minlimit=6 preferedwidth=10 checkconnectedcopper=TRUE
14 further rules are at their usual default settings.

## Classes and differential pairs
component class SR135B_Hardware: !PCB FID1 FID2 FID3 FID4 H1 H2 H3 H4 Logo4 Logo5 Logo6 MP1 MP2 MP3 MP4 SH-JP1 SH-JP2 SH-JP3 SH-JP4 SH-JP5 SH-JP6 SH-JP7 SH-JP8 SH-JP9 SH-JP10 SH-JP11 SH-JP12 ZZ2 ZZ3 ZZ4
component class FiducialMark: FID1 FID2 FID3 FID4
component class AssemblyNote: ZZ2 ZZ3 ZZ4
component class Header: J3 J4 J11 JP1 JP2 JP3 JP4 JP5 JP6 JP7 JP8 JP9 JP10 JP11 JP12

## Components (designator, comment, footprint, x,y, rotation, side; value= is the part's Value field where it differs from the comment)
C1 "GRM188R72A104KA35D" FP-GRM188R72A104KA35D_0603-MFG 1955,1000 r90 top
C2 "GRM188R72A104KA35D" FP-GRM188R72A104KA35D_0603-MFG 1940,783.46 r180 top
C3 "C3225X7R2A106K250AC" FP-C3225X7R2A106K250AC_1210-MFG 3260.59,761.15 r270 top value=10µF
C4 "A768KE276M1JLAE054" FP-A768KE276M1JLAE054_SMT_CAP_8MM3_8MM3-0 2972.24,915.59 r180 top value=27µF
C5 "C3225X7R2A106K250AC" FP-C3225X7R2A106K250AC_1210-MFG 2980,1900 r270 top value=10µF
C6 "C3225X7R2A106K250AC" FP-C3225X7R2A106K250AC_1210-MFG 2860,1900 r270 top value=10µF
C7 "A768KE276M1JLAE054" FP-A768KE276M1JLAE054_SMT_CAP_8MM3_8MM3-0 2972.24,1275.59 r180 top value=27µF
C8 "GRM188R72A104KA35D" FP-GRM188R72A104KA35D_0603-MFG 3805,768.07 r270 top
C9 "C3225X7R2A106K250AC" FP-C3225X7R2A106K250AC_1210-MFG 1162.24,2125.59 r0 top value=10µF
C10 "GRM188R72A104KA35D" FP-GRM188R72A104KA35D_0603-MFG 2455,1925 r270 top
C11 "GCJ188R72A104KA01D" 0603 305,760 r90 top value=0.1uF
C12 "GCM188L81H104KA57D" FP-GCM188L81H104KA57D_0603-MFG 1332.24,2299.02 r90 top
C13 "GRM188R72A104KA35D" FP-GRM188R72A104KA35D_0603-MFG 2525,1925 r270 top
C14 "C3225X7R2A106K250AC" FP-C3225X7R2A106K250AC_1210-MFG 1157.24,1991.73 r0 top value=10µF
C15 "GRM155R62A104KE14D" 0402S 3015,2660 r0 top value=0.1uF
C16 "GRM155R62A104KE14D" 0402S 2355,3085 r0 top value=0.1uF
C17 "A768KE276M1JLAE054" FP-A768KE276M1JLAE054_SMT_CAP_8MM3_8MM3-0 1132.24,1625.59 r0 top value=27µF
C18 "A768KE276M1JLAE054" FP-A768KE276M1JLAE054_SMT_CAP_8MM3_8MM3-0 1132.24,1265.59 r0 top value=27µF
C19 "A768KE276M1JLAE054" FP-A768KE276M1JLAE054_SMT_CAP_8MM3_8MM3-0 1132.24,905.59 r0 top value=27µF
C20 "C3225X7R2A106K250AC" FP-C3225X7R2A106K250AC_1210-MFG 1157.24,1866.73 r0 top value=10µF
C21 "C3225X7R2A106K250AC" FP-C3225X7R2A106K250AC_1210-MFG 2620,1900 r270 top value=10µF
C22 "C3225X7R2A106K250AC" FP-C3225X7R2A106K250AC_1210-MFG 2740,1900 r270 top value=10µF
C23 "A768KE276M1JLAE054" FP-A768KE276M1JLAE054_SMT_CAP_8MM3_8MM3-0 2972.24,1635.59 r180 top value=27µF
C24 "GRM155R71H104ME14D" 0402S 2335,3025 r270 top value=0.1uF
C25 "GRM1555C1H271JA01D" 0402S 2335,2955 r270 top value=270pF
C26 "GRT188R61A226ME13D" 0603S 2750,2680 r90 top value=22µF
C27 "GRT188R61A226ME13D" 0603S 2375,2780 r270 top value=22µF
C28 "CGA3E3X7S2A104K080AB" 0603S 2695,2680 r90 top value=0.1uF
C29 "GRM155R71H104ME14D" 0402S 2800,2625 r90 top value=0.1uF
C30 "08051A681JAT2A" 0805_HV1 1581.75,1948.24 r90 top value=680pF
C31 "GCM155R71H104KE02D" 0402S 2380,2895 r270 top value=0.1uF
C32 "C0805C102J1GACTU" 0805_HV1 2060,1837.59 r90 top value=1000pF
C33 "GCM155R71H104KE02D" 0402S 2470,2705 r180 top value=0.1uF
C34 "06035A221FAT2A" 0603S 2550,3200 r180 top value=220pF
C35 "06035A560FAT2A" 0603S 2769.68,3195 r180 top value=56pF
C36 "C0603C123K5RACTU" 0603S 2550,3260 r180 top value=0.012uF
C37 "CC0603KRX7R9BB203" 0603S 2835,2705 r0 top value=0.02uF
C38 "06031C472JAT2A" 0603S 2470,3115 r90 top value=4700pF
C39 "06035C473JAT2A" 0603S 2440,3190 r0 top value=0.047uF
C40 "C3225X7R2A106K250AC" FP-C3225X7R2A106K250AC_1210-MFG 1242.2,2284.88 r270 top value=10µF
C41 "C3225X7R2A106K250AC" FP-C3225X7R2A106K250AC_1210-MFG 2462.5,655.91 r180 top value=10µF
C42 "C0603C472K5RACTU" 0603S 2132,1646.23 r270 top value=4700pF
C43 "C0603C681J5GACTU" 0603S 2592.17,2533.03 r0 top value=680pF
C44 "C0603C681J5GACTU" 0603S 2601.5,2260 r0 top value=680pF
D1 "BAS70-04-E3-18" FP-BAS70-04-E3-18_SOT23-3-MFG 1955,888.46 r180 top
D2 "MMSZ4697T1G" SOD-123 2441.18,825.61 r0 top value=10V
D3 "SMBJ48A-13-F" SMB 1855.08,475.59 r180 bottom value=48V
D4 "SMBJ48A-13-F" SMB 2432.24,675.59 r0 bottom value=48V
FID1 "Fiducial" Fiducial10-20 527.43,3342.43 r0 top
FID2 "Fiducial" Fiducial10-20 860.46,140 r0 top
FID3 "Fiducial" Fiducial10-20 3183,140 r0 top
FID4 "Fiducial" Fiducial10-20 3300,3003.88 r0 top
H1 "PMSSS 440 0025 PH" B_F_PMSSS4400025PH 200,200 r0 top
H2 "PMSSS 440 0025 PH" B_F_PMSSS4400025PH 200,3400 r0 top
H3 "PMSSS 440 0025 PH" B_F_PMSSS4400025PH 3900,200 r0 top
H4 "PMSSS 440 0025 PH" B_F_PMSSS4400025PH 3900,3400 r0 top
J1 "108-0740-001" Johnson_108-0740-001 3505,440 r0 top
J2 "108-0740-001" Johnson_108-0740-001 600,440 r0 top
J3 "61300611121" WURTH_61300611121 205,760 r90 top
J4 "61300611121" WURTH_61300611121 3905,768.07 r90 top
J5 "108-0740-001" Johnson_108-0740-001 3505,1095 r0 top
J6 "108-0740-001" Johnson_108-0740-001 600,1085 r0 top
J7 "SSW-105-02-G-D-RA" FP-SSW-105-02-G-D-RA_HDR10-MFG 1142.09,163.07 r0 bottom
J9 "XT30PW-F" FP-XT30PW-F_CONN_SOCKET_DC2-MFG 1843.66,-40.46 r0 bottom
J10 "XT30PW-M" FP-XT30PW-M_CONN_PLUG2-MFG 2443.66,172.8 r0 bottom
J11 "61300211121" WURTH_61300211121 3850,3000 r0 top
J12 "N2510-6002-RB" CONN_2510-6002 1350,3350 r0 top
JP1 "61300311121" WURTH_61300311121 3800,1800 r0 top
JP2 "61300511121" Wurth_61300511121 3300,3248.86 r0 top
JP3 "61300311121" WURTH_61300311121 3800,1950 r180 top
JP4 "61300311121" WURTH_61300311121 3800,2100 r180 top
JP5 "61300311121" WURTH_61300311121 3800,3150 r180 top
JP6 "61300211121" WURTH_61300211121 3850,2250 r0 top
JP7 "61300311121" WURTH_61300311121 3400,3400 r0 top
JP8 "61300211121" WURTH_61300211121 3850,2700 r0 top
JP9 "61300311121" WURTH_61300311121 3800,2845 r180 top
JP10 "61300211121" WURTH_61300211121 3850,2400 r0 top
JP11 "61300211121" WURTH_61300211121 3850,2550 r0 top
JP12 "61300211121" WURTH_61300211121 1950,3400 r0 top
L1 "XAL1580-532MEB" XAL1580 1993.27,2259.41 r0 top value=5.3uH
LOGO4 "WEEE logo" WEEE_Minimum 156.74,2393 r0 top (schematic designator Logo4)
Logo5 "CAUTION HOT SURFACE" IEC_HotSurface_Small 1931.89,2760 r0 top
Logo6 "CAUTION.  READ USER GUIDE BEFORE USE" IEC_Caution_Small 147.81,2813.29 r0 top
MP1 "1902D_Ndrill" FP-1902D_Ndrill_HEX_STANDOFF-MFG 3900,200 r180 bottom
MP2 "1902D_Ndrill" FP-1902D_Ndrill_HEX_STANDOFF-MFG 200,200 r180 bottom
MP3 "1902D_Ndrill" FP-1902D_Ndrill_HEX_STANDOFF-MFG 3900,3400 r180 bottom
MP4 "1902D_Ndrill" FP-1902D_Ndrill_HEX_STANDOFF-MFG 200,3400 r180 bottom
NT3 "Net-Tie" Net-Tie_10mil 2440.26,2815.5 r0 top net-tie
Q1 "CSD18540Q5B" DNK0008A 2150,857.4 r270 top value=60V
Q2 "ISZ034N06LM5ATMA1" FP-ISZ034N06LM5ATMA1_TSDSON8-MFG 1455,2210 r90 top
Q3 "SI7415DN-T1-GE3" PowerPAK_1212-8 2390,956.14 r90 top value=-60V
Q4 "ISZ034N06LM5ATMA1" FP-ISZ034N06LM5ATMA1_TSDSON8-MFG 1455,2000 r90 top
Q5 "ISC0703NLSATMA1" FP-ISC0702NLSATMA1_SuperSO8-5x6-MFG 2277.91,1810.87 r270 top
Q6 "ISZ034N06LM5ATMA1" FP-ISZ034N06LM5ATMA1_TSDSON8-MFG 1505,2425 r270 top
Q7 "ISC0703NLSATMA1" FP-ISC0702NLSATMA1_SuperSO8-5x6-MFG 2450,2400 r90 top
Q8 "ISC0703NLSATMA1" FP-ISC0702NLSATMA1_SuperSO8-5x6-MFG 2450,2125 r90 top
R1 "RC0603FR-075K1L" 0603S 2015.1,1003.97 r90 top value=5.10k
R2 "RMCF0603ZT0R00" 0603S 3450,3143 r0 top value=0
R3 "KRL2012E-C-R010-F-T05" FP-KRL2012E-C-R010-F-T05_0508-MFG 2415,1095 r270 top value=10m
R4 "KRL2012E-M-R005-F-T5" FP-KRL2012E-M-R005-F-T5_0805_WIDE-MFG 1610.88,2133.7 r180 top value=5m
R5 "CRCW0603180KJNEA" 0603S 2485,748.46 r180 top value=180k
R6 "KRL2012E-M-R005-F-T5" FP-KRL2012E-M-R005-F-T5_0805_WIDE-MFG 1610.3,2266.3 r180 top value=5m
R7 "RMCF0603ZT0R00" 0603S 3030,2610 r180 top value=0
R8 "RC0603FR-0710RL" 0603S 3150,3150 r180 top value=10.0
R9 "RMCF0603ZT0R00" 0603S 2345,3160 r90 top value=0
R10 "RMCF0603ZT0R00" 0603S 2525,3115 r270 top value=0
R11 "CRCW060343K0JNEA" 0603S 2527.46,934.46 r270 bottom value=43k
R12 "RC0603FR-0782KL" 0603S 2635,3115 r90 top value=82.0k
R13 "CRCW06033R00JNEA" 0603S 1475,2105 r0 top value=3.0
R14 "CRCW06033R00JNEA" 0603S 1475,2315 r0 top value=3.0
R15 "RMCF0603ZT0R00" 0603S 2265,3020 r180 top value=0
R16 "RMCF0603ZT0R00" 0603S 2265,3075 r180 top value=0
R17 "CRCW060310R0FKEAHP" 0603S 2265,2910 r180 top value=10.0
R18 "CRCW060310R0FKEAHP" 0603S 2265,2965 r180 top value=10.0
R19 "RC0603FR-074K3L" 0603S 2580,3115 r270 top value=4.30k
R20 "RMCF0603ZT0R00" 0603S 2202.97,1668.96 r180 top value=0
R21 "RC0603FR-0775KL" 0603S 2930,2610 r0 top value=75.0k
R22 "RC0603FR-0712K7L" 0603S 2850,2630 r270 top value=12.7k
R23 "CRCW12063R00JNEA" 1206L 1588.95,1780.5 r270 top value=3.0
R24 "RMCF0603ZT0R00" 0603S 2835,2760 r180 top value=0
R25 "RT0603BRD0710KL" 0603S 2750,3115 r90 top value=10.0k
R26 "CRCW12063R00JNEA" 1206L 2060,1662.87 r270 top value=3.0
R27 "RMCF0603ZT0R00" 0603S 2835,2815 r180 top value=0
R28 "CRCW06033R00JNEA" 0603S 1395,2345 r270 top value=3.0
R29 "CRCW06037K15FKEA" 0603S 2635,3230 r270 top value=7.15k
R30 "CRCW060340K2FKEA" 0603S 2805,3115 r270 top value=40.2k
R31 "RC0603FR-0797K6L" 0603S 2695,3115 r270 top value=97.6k
R32 "CRCW06033R90JNEA" 0603S 2491.4,2535 r0 top value=3.9
R33 "CRCW06033R90JNEA" 0603S 2499.23,2261.97 r0 top value=3.9
R34 "CRCW060320K0FKEA" 0603S 2415,3115 r270 top value=20.0k
R35 "RMCF0603ZT0R00" 0603S 2640,2680 r270 top value=0
R36 "RMCF0603ZT0R00" 0603S 2865,3115 r270 top value=0
R37 "CRCW06032K70JNEA" 0603S 2835,2980 r180 top value=2.7k
R38 "RMCF0603ZT0R00" 0603S 2835,3035 r0 top value=0
R39 "RC0603FR-072KL" 0603S 1625,3255 r270 bottom value=2.00k
R40 "RC0603FR-072KL" 0603S 1685,3255 r270 bottom value=2.00k
R41 "CRCW06033K83FKEA" 0603S 2835,2870 r180 top value=3.83k
R42 "RC0603FR-078K25L" 0603S 2835,2925 r180 top value=8.25k
R43 "TNPW060310K0BEEA" TNPW0603 1909.14,1700 r90 top value=10.0k
RT1 "TMP6131DECR" DEC0002A-MFG 1966.58,1732.48 r270 top value=10k
SH-JP1 "M7582-05" Harwin_M7582-05 3748.45,1800 r180 top
SH-JP2 "M7582-05" Harwin_M7582-05 3450,3248.86 r180 top
SH-JP3 "M7582-05" Harwin_M7582-05 3847.9,1950 r180 top
SH-JP4 "M7582-05" Harwin_M7582-05 3847.9,2100.82 r180 top
SH-JP5 "M7582-05" Harwin_M7582-05 3850,3150 r180 top
SH-JP6 "M7582-05" Harwin_M7582-05 3846.83,2250 r180 top
SH-JP7 "M7582-05" Harwin_M7582-05 3450,3400 r180 top
SH-JP8 "M7582-05" Harwin_M7582-05 3847.9,2700 r180 top
SH-JP9 "M7582-05" Harwin_M7582-05 3850,2845 r180 top
SH-JP10 "M7582-05" Harwin_M7582-05 3848.9,2400 r180 top
SH-JP11 "M7582-05" Harwin_M7582-05 3848.9,2549.95 r180 top
SH-JP12 "M7582-05" Harwin_M7582-05 1947.89,3400 r180 top
TP1 "5013" Keystone5013 2650,1175 r90 top
TP2 "5013" Keystone5013 2650,1015 r90 top
TP3 "5010" Keystone5010 200,1410 r0 top
TP4 "5001" Keystone5001 2950,3400 r180 top
TP5 "5012" Keystone5012 1745,1835 r270 top
TP6 "5128" Keystone5128 1920,1835 r270 top
TP7 "5001" Keystone5001 2300,3400 r0 top
TP8 "5011" Keystone5011 200,1650 r270 top
TP9 "5004" Keystone5004 3650,3400 r90 top
TP10 "5004" Keystone5004 2150,3400 r0 top
TP11 "5004" Keystone5004 3900,1650 r0 top
TP12 "5004" Keystone5004 3100,3400 r180 top
TP13 "5004" Keystone5004 3900,1500 r0 top
U1 "LM251772RHAR" RHA0040P-MFG 2540,2865 r180 top
ZZ2 "These assemblies are ESD sensitive, ESD precautions shall be observed." AssemblyNote 200,4000 r0 top
ZZ3 "These assemblies must be clean and free from flux and all contaminants. Use of no clean flux is not acceptable." AssemblyNote 200,3900 r0 top
ZZ4 "These assemblies must comply with workmanship standards IPC-A-610 Class 2, unless otherwise specified." AssemblyNote 200,3800 r0 top

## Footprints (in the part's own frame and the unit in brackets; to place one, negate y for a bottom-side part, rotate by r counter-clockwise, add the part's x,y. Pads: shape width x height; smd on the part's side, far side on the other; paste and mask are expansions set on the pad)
0402S [mil] "Based on C0402S footprint from PADS legacy"
  rect 15x24 smd: 1(-20,0) 2(20,0)
  body extent -22,-12 22,12, height 24
0603 [mm] "0603 from SM-752 data"
  rect 1x0.95 smd: 1(-0.8,0) 2(0.8,0)
  silkscreen extent -1.52,-0.69 1.52,0.69, body extent -0.87,-0.47 0.87,0.47, height 1
0603S [mil]
  rect 20x35 smd: 1(-30,0) 2(30,0)
  body extent -34,-19 34,19, height 39
0805_HV1 [mm] "Custom footprint based on analyzing multiple manufacturer recommendations"
  rrect10% 1x1.25 smd: 1(-1,0) 2(1,0)
  silkscreen extent -0.2,-0.75 0.2,0.75, body extent -1.1,-0.72 1.1,0.73, height 1.45
1206L [mm] "1206 from SM-752 data"
  rect 1.1x1.75 smd: 1(-1.35,0) 2(1.35,0)
  silkscreen extent -0.4,-0.77 0.4,0.77, body extent -1.7,-0.9 1.7,0.9, height 1.35
AssemblyNote [mil] "Assembly Note"
B_F_PMSSS4400025PH [mil] "MACHINE SCREW PAN PHILLIPS 4-40"
  round 230 hole 125: 1(0,0)
  body extent -109,-109 110,110, height 79
CONN_2510-6002 [mm] "3M 2500 series TS-0770-L December 15, 2011"
  rect 1.65x1.65 hole 1.016 mask+0: 1(-5.08,-1.27)
  round 1.65 hole 1.016 mask+0: 2(-5.08,1.27) 3(-2.54,-1.27) 4(-2.54,1.27) 5(0,-1.27) 6(0,1.27) 7(2.54,-1.27) 8(2.54,1.27) 9(5.08,-1.27) 10(5.08,1.27)
  silkscreen extent -10.01,-4.17 10.01,4.47, body extent -10.01,-4.11 10.01,4.52, height 9.92
DEC0002A-MFG [mm]
  rrect40% 0.25x0.5 smd paste-1000 mask+0: 1(-0.325,0) 2(0.325,0)
  silkscreen extent -0.98,0.15 -0.83,0.3, body extent -0.63,-0.43 0.63,0.43, height 0.25
DNK0008A [mm] "SON, 8-Leads, Body 5x6mm"
  rrect39% 0.86x0.51 smd paste-0.05 mask-0.05: 1(-2.82,1.905) 2(-2.82,0.635) 3(-2.82,-0.635) 4(-2.82,-1.905) 5(2.82,-1.905) 6(2.82,-0.635) 7(2.82,0.635) 8(2.82,1.905)
  rrect40% 0.25x0.555 on Top Paste: 9(-0.83,2.372) 9(-0.83,-2.372)
  rrect40% 0.25x0.555 on Top Solder: 9(-0.83,2.372) 9(-0.83,-2.372)
  rrect11% 0.95x1.13 on Top Paste: 9(-0.535,1.33) 9(-0.535,0) 9(-0.535,-1.33) 9(0.615,1.33) 9(0.615,0) 9(0.615,-1.33) 9(1.765,1.33) 9(1.765,0) 9(1.765,-1.33)
  rrect3% 3.58x4 on Top Solder: 9(0.75,0)
  rrect5% 4.34x5.4 smd paste-3 mask-3: 9(1.08,0)
  body extent -3.05,-2.55 3.05,2.55, height 1.06
Fiducial10-20 [mm]
  round 1 smd mask+0.5: 1(0,0)
  Top Layer keep-out circle w1.178: c0,0 r0.5
FP-1902D_Ndrill_HEX_STANDOFF-MFG [mil]
  body extent -144,-125 144,125, height 765
FP-A768KE276M1JLAE054_SMT_CAP_8MM3_8MM3-0 [mm]
  rrect5% 4.2x2.2 smd paste+0 mask+0: 1(-3.65,0) 2(3.65,0)
  silkscreen extent -4.25,-4.25 4.25,4.25, body extent -6,-4.5 6,4.5, height 0.25
FP-BAS70-04-E3-18_SOT23-3-MFG [mm]
  rrect14% 0.9x0.7 smd paste+0 mask+0: 1(-1,0.95) 2(-1,-0.95) 3(1,0)
  silkscreen extent -0.71,-1.55 0.71,1.55, body extent -1.24,-1.48 1.24,1.48, height 1.15
FP-C3225X7R2A106K250AC_1210-MFG [mm]
  rrect9% 1.1x2.2 smd paste+0 mask+0: 1(-1.65,0) 2(1.65,0)
  silkscreen extent -0.72,-1.43 0.72,1.43, body extent -2.3,-1.53 2.3,1.53, height 0.25
FP-GCM188L81H104KA57D_0603-MFG [mm]
  rrect15% 0.65x0.7 smd paste+0 mask+0: 1(-0.675,0) 2(0.675,0)
  body extent -1.1,-0.55 1.1,0.55, height 0.25
FP-GRM188R72A104KA35D_0603-MFG [mm]
  rrect15% 0.65x0.7 smd paste+0 mask+0: 1(-0.675,0) 2(0.675,0)
  silkscreen extent -0.85,-0.72 0.85,0.72, body extent -0.8,-0.4 0.8,0.4, height 0.9
FP-ISC0702NLSATMA1_SuperSO8-5x6-MFG [mm]
  rrect20% 0.5x0.925 smd paste-1000 mask+0: 1(-1.905,-2.865) 2(-0.635,-2.865) 3(0.635,-2.865) 4(1.905,-2.865)
  rrect2% 4.41x4.455 smd paste-1000 mask-1000: 5-6-7-8(0,1.098)
  silkscreen extent -2.68,-4 2.68,3.05, body extent -2.88,-3.43 2.88,3.43, height 0.25
FP-ISZ034N06LM5ATMA1_TSDSON8-MFG [mm]
  round 0.81 smd paste-1000 mask-1000: 1-2-3(-0.325,-1.45)
  rrect29% 0.34x0.9 smd paste-1000 mask+0: 4(0.975,-1.45)
  round 2.061 smd paste-1000 mask-1000: 5-6-7-8(0,0.72)
  Top Layer region: -1.145,-1 0.495,-1 0.495,-1.9 -1.145,-1.9
  Top Layer region: -1.145,-0.46 1.145,-0.46 1.145,1.9 -1.145,1.9
  silkscreen extent -1.7,-2.58 1.7,1.7, body extent -1.8,-2 1.8,2, height 0.25
FP-KRL2012E-C-R010-F-T05_0508-MFG [mm]
  rrect14% 0.7x2.2 smd paste+0 mask+0: 1(-0.65,0) 2(0.65,0)
  silkscreen extent -0.72,-1.5 0.72,1.5, body extent -1.1,-1.2 1.1,1.2, height 0.25
FP-KRL2012E-M-R005-F-T5_0805_WIDE-MFG [mm]
  rrect14% 0.7x2.2 smd paste+0 mask+0: 1(-0.65,0) 2(0.65,0)
  silkscreen extent -0.72,-1.5 0.72,1.5, body extent -1.1,-1.2 1.1,1.2, height 0.25
FP-SSW-105-02-G-D-RA_HDR10-MFG [mm]
  rrect6% 1.59x1.59 hole 1.04 paste-2539.97 mask+0: 1(-5.08,-5.779)
  round 1.59 hole 1.04 paste-2539.97 mask+0: 2(-5.08,-8.319) 3(-2.54,-5.779) 4(-2.54,-8.319) 5(0,-5.779) 6(0,-8.319) 7(2.54,-5.779) 8(2.54,-8.319) 9(5.08,-5.779) 10(5.08,-8.319)
  silkscreen extent -6.73,-5.9 6.73,4.39, body extent -6.61,-8.52 6.61,4.25, height 5.08
FP-XT30PW-F_CONN_SOCKET_DC2-MFG [mm]
  rrect4% 2.6x2.6 hole 1.7 paste-2539.97 mask+0: 1(-2.5,-8.825)
  round 2.6 hole 1.7 paste-2539.97 mask+0: 2(2.5,-8.825)
  round 1.55 hole 1 paste-2539.97 mask+0: 3(-5.5,-3.825) 4(5.5,-3.825)
  silkscreen extent -6.65,-8.95 6.65,5.07, body extent -6.65,-9.83 6.65,5.07, height 5
FP-XT30PW-M_CONN_PLUG2-MFG [mm]
  rrect4% 2.6x2.6 hole 1.7 paste-2539.97 mask+0: 1(2.5,-8.6)
  round 2.6 hole 1.7 paste-2539.97 mask+0: 2(-2.5,-8.6)
  round 1.55 hole 1 paste-2539.97 mask+0: 3(-5.5,1.4) 4(5.5,1.4)
  silkscreen extent -6.65,-8.72 6.65,4.5, body extent -6.65,-9.45 6.65,4.5, height 5.1
Harwin_M7582-05 [mil] "Single Operation 2.54mm Pitch Open Top Jumper Socket"
  body extent -98,-47 98,47, height 236
IEC_Caution_Small [mil]
  silkscreen extent -107,-93 107,92
IEC_HotSurface_Small [mil]
  silkscreen extent -107,-93 107,92
Johnson_108-0740-001 [mm] "Banana Jack Uninsulated Standard Type"
  round 12 hole 6.858: 1(0,0)
  body extent -4.77,-5.43 4.75,5.57, height 2.39
Keystone5001 [mil] "For Keystone 500x miniature loop terminals"
  round 80 hole 40: 1(0,0)
  silkscreen extent -52,-52 52,52, body extent -49,-49 49,49, height 182
Keystone5004 [mil] "For Keystone 500x miniature loop terminals"
  round 80 hole 40: 1(0,0)
  silkscreen extent -52,-52 52,52, body extent -49,-49 49,49, height 182
Keystone5010 [mil] "Keystone Multipurpose loops"
  round 87 hole 63: 1(0,0)
  silkscreen extent -70,-70 70,70, body extent -63,-63 63,62, height 319
Keystone5011 [mil] "Keystone Multipurpose loops"
  round 87 hole 63: 1(0,0)
  silkscreen extent -70,-70 70,70, body extent -63,-63 63,62, height 319
Keystone5012 [mil] "Keystone Multipurpose loops"
  round 87 hole 63: 1(0,0)
  silkscreen extent -70,-70 70,70, body extent -63,-63 63,62, height 319
Keystone5013 [mil] "Keystone Multipurpose loops"
  round 87 hole 63: 1(0,0)
  silkscreen extent -70,-70 70,70, body extent -63,-63 63,62, height 319
Keystone5128 [mil] "Keystone Multipurpose loops"
  round 87 hole 63: 1(0,0)
  silkscreen extent -70,-70 70,70, body extent -63,-63 63,62, height 319
Net-Tie_10mil [mil] "10mil net tie, no solder mask opening, no solder paste"
  rect 10x10 smd paste-5 mask-5: 1(-10,0) 2(10,0)
  Top Layer region: -6,5 6,5 6,-5 -6,-5
PowerPAK_1212-8 [mm] "Vishay PowerPAK 1212-8, Body 3.4x3.2mm (max), Pitch 0.65mm, IPC Medium Density"
  rrect50% 0.73x0.4 smd paste-0.05 mask-0.05: 1(-1.535,0.991) 2(-1.535,0.33) 3(-1.535,-0.33) 4(-1.535,-0.991)
  rrect50% 0.71x0.4 smd paste-0.05 mask-0.05: 5(1.545,-0.991) 6(1.545,-0.33) 7(1.545,0.33) 8(1.545,0.991)
  rrect30% 0.33x0.6 on Top Paste: 9(-0.195,1.55) 9(-0.195,-1.55)
  rrect30% 0.33x3.7 on Top Solder: 9(-0.195,0)
  rrect11% 1.3x0.94 on Top Paste: 9(0.39,0.57) 9(0.39,-0.57)
  rrect6% 1.6x2.28 on Top Solder: 9(0.54,0)
  rrect9% 2.31x3.3 smd paste-2 mask-2: 9(0.745,0)
  Top Layer region: -0.41,-1.8 -0.41,1.8 -0.402,1.838 -0.381,1.871 -0.348,1.892 -0.31,1.9 -0.31,1.9 -0.08,1.9 -0.042,1.892 -0.009,1.871 0.012,1.838 0.02,1.8 0.02,1.8 0.02,-1.8 0.012,-1.838 -0.009,-1.871 -0.042,-1.892 -0.08,-1.9 -0.08,-1.9 -0.31,-1.9 -0.348,-1.892 -0.381,-1.871 -0.402,-1.838 -0.41,-1.8
  silkscreen extent -1.75,-1.75 1.75,1.75, body extent -1.65,-1.66 1.65,1.64, height 1.08
RHA0040P-MFG [mm]
  rrect40% 0.6x0.25 smd paste+0 mask+0: 1(-2.9,2.25) 2(-2.9,1.75) 3(-2.9,1.25) 4(-2.9,0.75) 5(-2.9,0.25) 6(-2.9,-0.25) 7(-2.9,-0.75) 8(-2.9,-1.25) 9(-2.9,-1.75) 10(-2.9,-2.25) 21(2.9,-2.25) 22(2.9,-1.75) 23(2.9,-1.25) 24(2.9,-0.75) 25(2.9,-0.25) 26(2.9,0.25) 27(2.9,0.75) 28(2.9,1.25) 29(2.9,1.75) 30(2.9,2.25)
  rrect40% 0.25x0.6 smd paste+0 mask+0: 11(-2.25,-2.9) 12(-1.75,-2.9) 13(-1.25,-2.9) 14(-0.75,-2.9) 15(-0.25,-2.9) 16(0.25,-2.9) 17(0.75,-2.9) 18(1.25,-2.9) 19(1.75,-2.9) 20(2.25,-2.9) 31(2.25,2.9) 32(1.75,2.9) 33(1.25,2.9) 34(0.75,2.9) 35(0.25,2.9) 36(-0.25,2.9) 37(-0.75,2.9) 38(-1.25,2.9) 39(-1.75,2.9) 40(-2.25,2.9)
  rrect3% 3.3x3.3 smd paste-1000 mask+0: 41(0,0)
  silkscreen extent -3.88,-3.05 3.05,3.05, body extent -3.3,-3.3 3.3,3.3, height 0.25
SMB [mil] "Molded Diode, 2-Leads, Body 5.4x3.6mm, IPC Medium Density, based on OnSemi component dimensions"
  rect 85x107.99 smd: 1(-87.01,0) 2(87.01,0)
  silkscreen extent -155,-82 125,82, body extent -106,-71 106,71, height 91
SOD-123 [mm] "On Semi recommended land pattern"
  rect 0.915x1.22 smd: 1(-1.637,0) 2(1.637,0)
  silkscreen extent -2.74,-1.17 2.03,1.17, body extent -1.93,-0.9 1.93,0.9, height 1.35
TNPW0603 [mm] "Vishay"
  rect 0.5x0.9 smd: 1(-0.75,0) 2(0.75,0)
  silkscreen extent -0.2,-0.6 0.2,0.6, body extent -0.85,-0.47 0.85,0.47, height 0.55
WEEE_Minimum [mil] "WEEElie bin"
  silkscreen extent -95,-172 99,104
WURTH_61300211121 [mm] "Header, 2.54mm, 2x1, TH"
  rrect50% 1.65x1.65 hole 1.15: 1(-1.27,0)
  round 1.65 hole 1.15: 2(1.27,0)
  body extent -2.54,-1.27 2.54,1.27, height 8.54
WURTH_61300311121 [mm] "Header, 2.54mm, 3x1, TH"
  rrect50% 1.65x1.65 hole 1.15: 1(-2.54,0)
  round 1.65 hole 1.15: 2(0,0) 3(2.54,0)
  body extent -3.81,-1.27 3.81,1.27, height 8.54
Wurth_61300511121 [mm] "Header, 2.54mm, 5x1, TH"
  rrect50% 1.65x1.65 hole 1.1: 1(-5.08,0)
  round 1.65 hole 1.1: 2(-2.54,0) 3(0,0) 4(2.54,0) 5(5.08,0)
  body extent -6.35,-1.27 6.35,1.27, height 8.54
WURTH_61300611121 [mm] "Header, 2.54mm, 6x1, TH"
  rrect50% 1.65x1.65 hole 1.15: 1(-6.35,0)
  round 1.65 hole 1.15: 2(-3.81,0) 3(-1.27,0) 4(1.27,0) 5(3.81,0) 6(6.35,0)
  body extent -7.62,-1.27 7.62,1.27, height 8.54
XAL1580 [mm] "COILCRAFT"
  rect 3.18x14.36 smd: 1(-5.3,0) 2(5.3,0)
  silkscreen extent -7.7,-7.8 7.7,7.8, body extent -7.7,-7.8 7.7,7.8, height 8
